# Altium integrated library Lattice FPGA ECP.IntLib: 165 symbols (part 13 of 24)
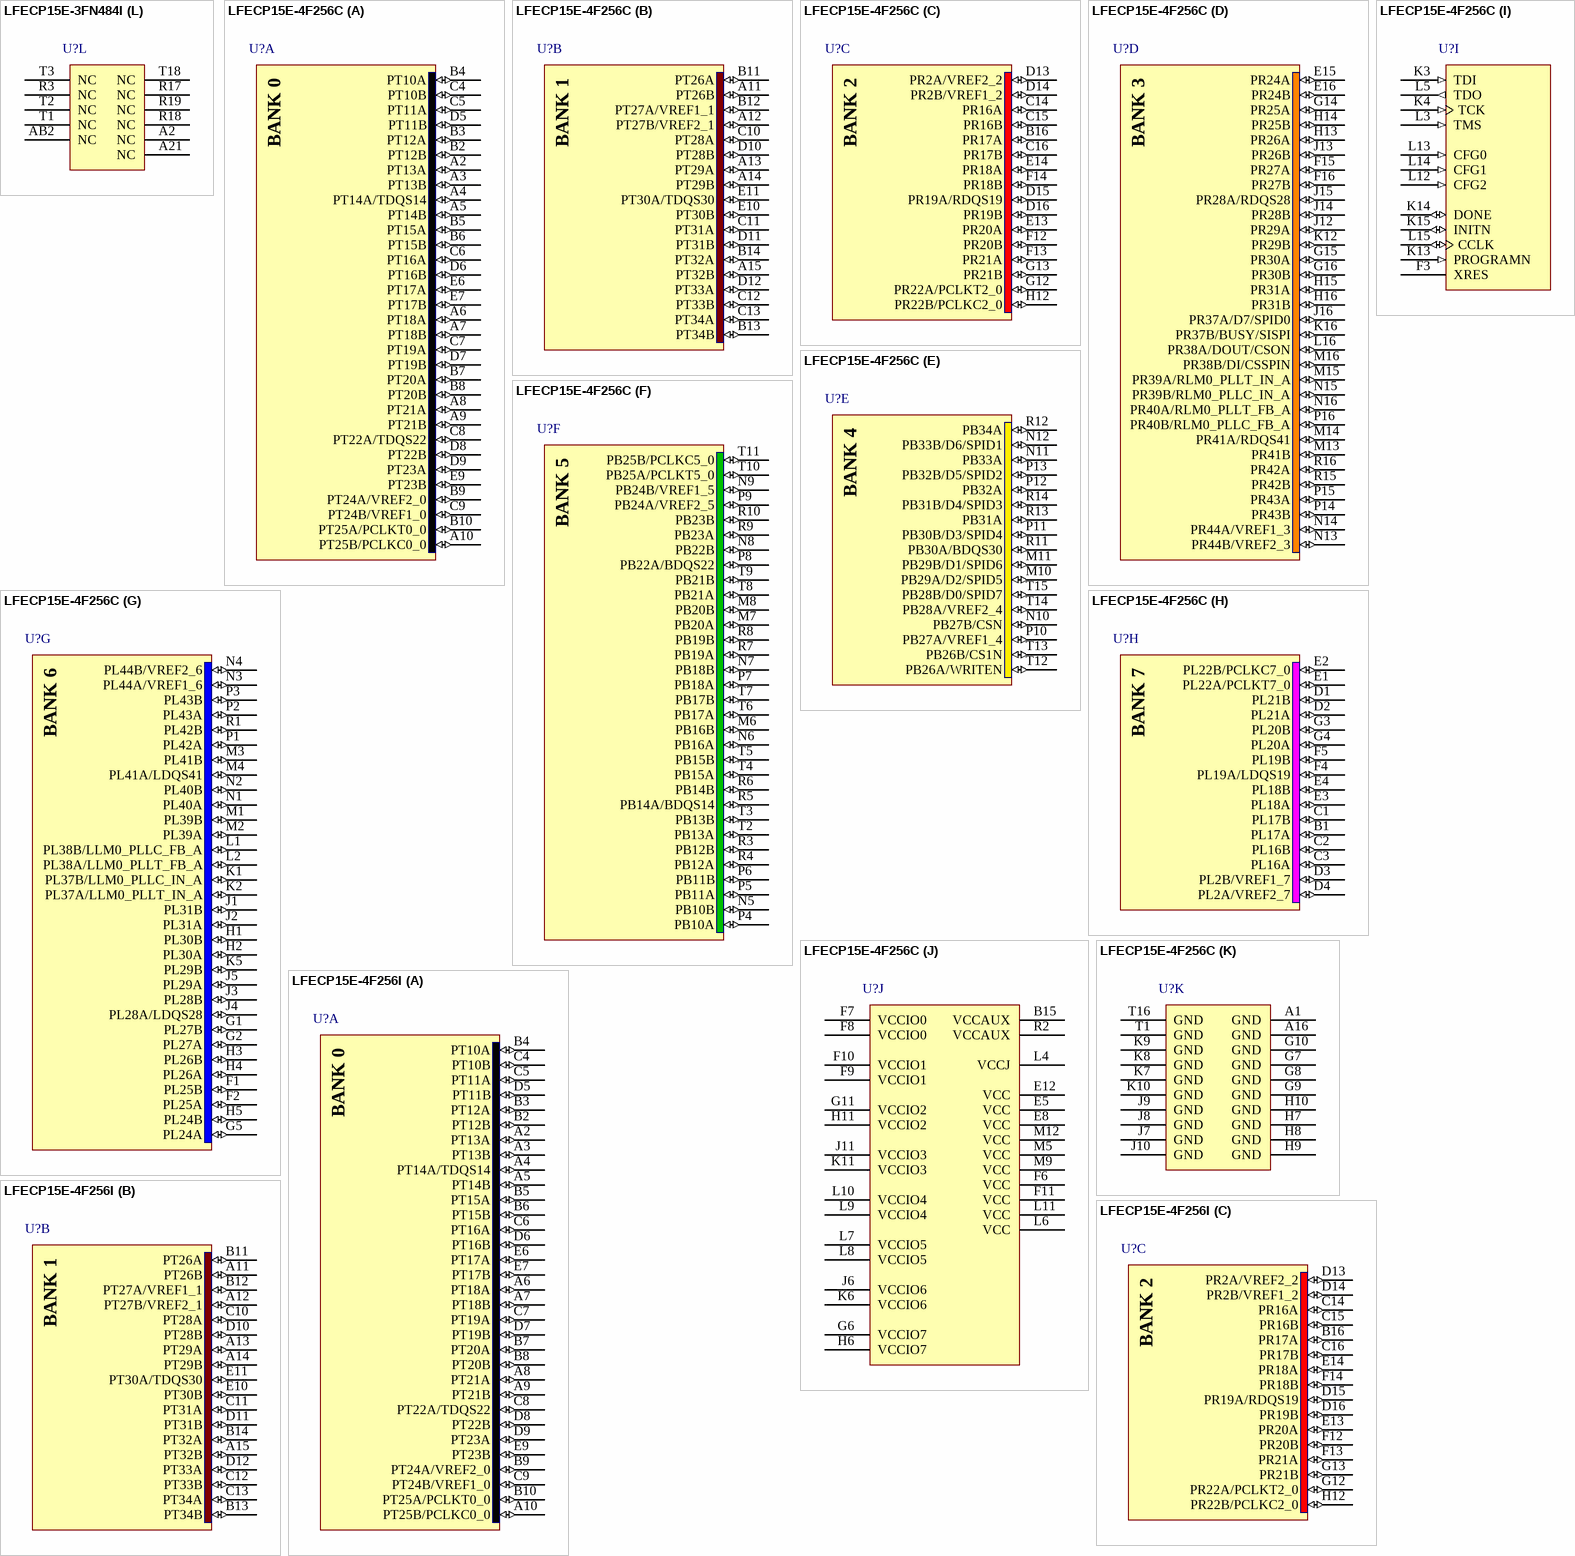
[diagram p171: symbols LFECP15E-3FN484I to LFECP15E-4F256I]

## LFECP15E-4F256C
designator U?
ECP 1.2V FPGA, 192 I/Os, 4 PLLs, 15.3K LUTs, 6 sysDSP Blocks, 24 18x18 Multipliers, 256-Pin fpBGA, Speed Grade 4, Commercial Temperature Grade
footprint fpBGA256 (BGA, 256-Leads, Body 17x17mm, Pitch 1mm)
3D model ECP15E-fpBGA256 (256-Ball Fine Pitch Ball Grid Array (fpBGA256))
part A pins: A2 PT13A (io), A3 PT13B (io), A4 PT14A/TDQS14 (io), A5 PT14B (io), A6 PT18A (io), A7 PT18B (io), A8 PT21A (io), A9 PT21B (io), A10 PT25B/PCLKC0_0 (io), B2 PT12B (io), B3 PT12A (io), B4 PT10A (io), B5 PT15A (io), B6 PT15B (io), B7 PT20A (io), B8 PT20B (io), B9 PT24A/VREF2_0 (io), B10 PT25A/PCLKT0_0 (io), C4 PT10B (io), C5 PT11A (io), C6 PT16A (io), C7 PT19A (io), C8 PT22A/TDQS22 (io), C9 PT24B/VREF1_0 (io), D5 PT11B (io), D6 PT16B (io), D7 PT19B (io), D8 PT22B (io), D9 PT23A (io), E6 PT17A (io), E7 PT17B (io), E9 PT23B (io)
part B pins: A11 PT26B (io), A12 PT27B/VREF2_1 (io), A13 PT29A (io), A14 PT29B (io), A15 PT32B (io), B11 PT26A (io), B12 PT27A/VREF1_1 (io), B13 PT34B (io), B14 PT32A (io), C10 PT28A (io), C11 PT31A (io), C12 PT33B (io), C13 PT34A (io), D10 PT28B (io), D11 PT31B (io), D12 PT33A (io), E10 PT30B (io), E11 PT30A/TDQS30 (io)
part C pins: B16 PR17A (io), C14 PR16A (io), C15 PR16B (io), C16 PR17B (io), D13 PR2A/VREF2_2 (io), D14 PR2B/VREF1_2 (io), D15 PR19A/RDQS19 (io), D16 PR19B (io), E13 PR20A (io), E14 PR18A (io), F12 PR20B (io), F13 PR21A (io), F14 PR18B (io), G12 PR22A/PCLKT2_0 (io), G13 PR21B (io), H12 PR22B/PCLKC2_0 (io)
part D pins: E15 PR24A (io), E16 PR24B (io), F15 PR27A (io), F16 PR27B (io), G14 PR25A (io), G15 PR30A (io), G16 PR30B (io), H13 PR26A (io), H14 PR25B (io), H15 PR31A (io), H16 PR31B (io), J12 PR29A (io), J13 PR26B (io), J14 PR28B (io), J15 PR28A/RDQS28 (io), J16 PR37A/D7/SPID0 (io), K12 PR29B (io), K16 PR37B/BUSY/SISPI (io), L16 PR38A/DOUT/CSON (io), M13 PR41B (io), M14 PR41A/RDQS41 (io), M15 PR39A/RLM0_PLLT_IN_A (io), M16 PR38B/DI/CSSPIN (io), N13 PR44B/VREF2_3 (io), N14 PR44A/VREF1_3 (io), N15 PR39B/RLM0_PLLC_IN_A (io), N16 PR40A/RLM0_PLLT_FB_A (io), P14 PR43B (io), P15 PR43A (io), P16 PR40B/RLM0_PLLC_FB_A (io), R15 PR42B (io), R16 PR42A (io)
part E pins: M10 PB29A/D2/SPID5 (io), M11 PB29B/D1/SPID6 (io), N10 PB27B/CSN (io), N11 PB33A (io), N12 PB33B/D6/SPID1 (io), P10 PB27A/VREF1_4 (io), P11 PB30B/D3/SPID4 (io), P12 PB32A (io), P13 PB32B/D5/SPID2 (io), R11 PB30A/BDQS30 (io), R12 PB34A (io), R13 PB31A (io), R14 PB31B/D4/SPID3 (io), T12 PB26A/WRITEN (io), T13 PB26B/CS1N (io), T14 PB28A/VREF2_4 (io), T15 PB28B/D0/SPID7 (io)
part F pins: M6 PB16B (io), M7 PB20A (io), M8 PB20B (io), N5 PB10B (io), N6 PB16A (io), N7 PB18B (io), N8 PB22B (io), N9 PB24B/VREF1_5 (io), P4 PB10A (io), P5 PB11A (io), P6 PB11B (io), P7 PB18A (io), P8 PB22A/BDQS22 (io), P9 PB24A/VREF2_5 (io), R3 PB12B (io), R4 PB12A (io), R5 PB14A/BDQS14 (io), R6 PB14B (io), R7 PB19A (io), R8 PB19B (io), R9 PB23A (io), R10 PB23B (io), T2 PB13A (io), T3 PB13B (io), T4 PB15A (io), T5 PB15B (io), T6 PB17A (io), T7 PB17B (io), T8 PB21A (io), T9 PB21B (io), T10 PB25A/PCLKT5_0 (io), T11 PB25B/PCLKC5_0 (io)
part G pins: F1 PL25B (io), F2 PL25A (io), G1 PL27B (io), G2 PL27A (io), G5 PL24A (io), H1 PL30B (io), H2 PL30A (io), H3 PL26B (io), H4 PL26A (io), H5 PL24B (io), J1 PL31B (io), J2 PL31A (io), J3 PL28B (io), J4 PL28A/LDQS28 (io), J5 PL29A (io), K1 PL37B/LLM0_PLLC_IN_A (io), K2 PL37A/LLM0_PLLT_IN_A (io), K5 PL29B (io), L1 PL38B/LLM0_PLLC_FB_A (io), L2 PL38A/LLM0_PLLT_FB_A (io), M1 PL39B (io), M2 PL39A (io), M3 PL41B (io), M4 PL41A/LDQS41 (io), N1 PL40A (io), N2 PL40B (io), N3 PL44A/VREF1_6 (io), N4 PL44B/VREF2_6 (io), P1 PL42A (io), P2 PL43A (io), P3 PL43B (io), R1 PL42B (io)
part H pins: B1 PL17A (io), C1 PL17B (io), C2 PL16B (io), C3 PL16A (io), D1 PL21B (io), D2 PL21A (io), D3 PL2B/VREF1_7 (io), D4 PL2A/VREF2_7 (io), E1 PL22A/PCLKT7_0 (io), E2 PL22B/PCLKC7_0 (io), E3 PL18A (io), E4 PL18B (io), F4 PL19A/LDQS19 (io), F5 PL19B (io), G3 PL20B (io), G4 PL20A (io)
part I pins: F3 XRES, K3 TDI (in), K4 TCK (in), K13 PROGRAMN (in), K14 DONE (io), K15 INITN (io), L3 TMS (in), L5 TDO (out), L12 CFG2 (in), L13 CFG0 (in), L14 CFG1 (in), L15 CCLK (io)
part J pins: B15 VCCAUX (power), E5 VCC (power), E8 VCC (power), E12 VCC (power), F6 VCC (power), F7 VCCIO0 (power), F8 VCCIO0 (power), F9 VCCIO1 (power), F10 VCCIO1 (power), F11 VCC (power), G6 VCCIO7 (power), G11 VCCIO2 (power), H6 VCCIO7 (power), H11 VCCIO2 (power), J6 VCCIO6 (power), J11 VCCIO3 (power), K6 VCCIO6 (power), K11 VCCIO3 (power), L4 VCCJ (power), L6 VCC (power), L7 VCCIO5 (power), L8 VCCIO5 (power), L9 VCCIO4 (power), L10 VCCIO4 (power), L11 VCC (power), M5 VCC (power), M9 VCC (power), M12 VCC (power), R2 VCCAUX (power)
part K pins: A1 GND (power), A16 GND (power), G7 GND (power), G8 GND (power), G9 GND (power), G10 GND (power), H7 GND (power), H8 GND (power), H9 GND (power), H10 GND (power), J7 GND (power), J8 GND (power), J9 GND (power), J10 GND (power), K7 GND (power), K8 GND (power), K9 GND (power), K10 GND (power), T1 GND (power), T16 GND (power)

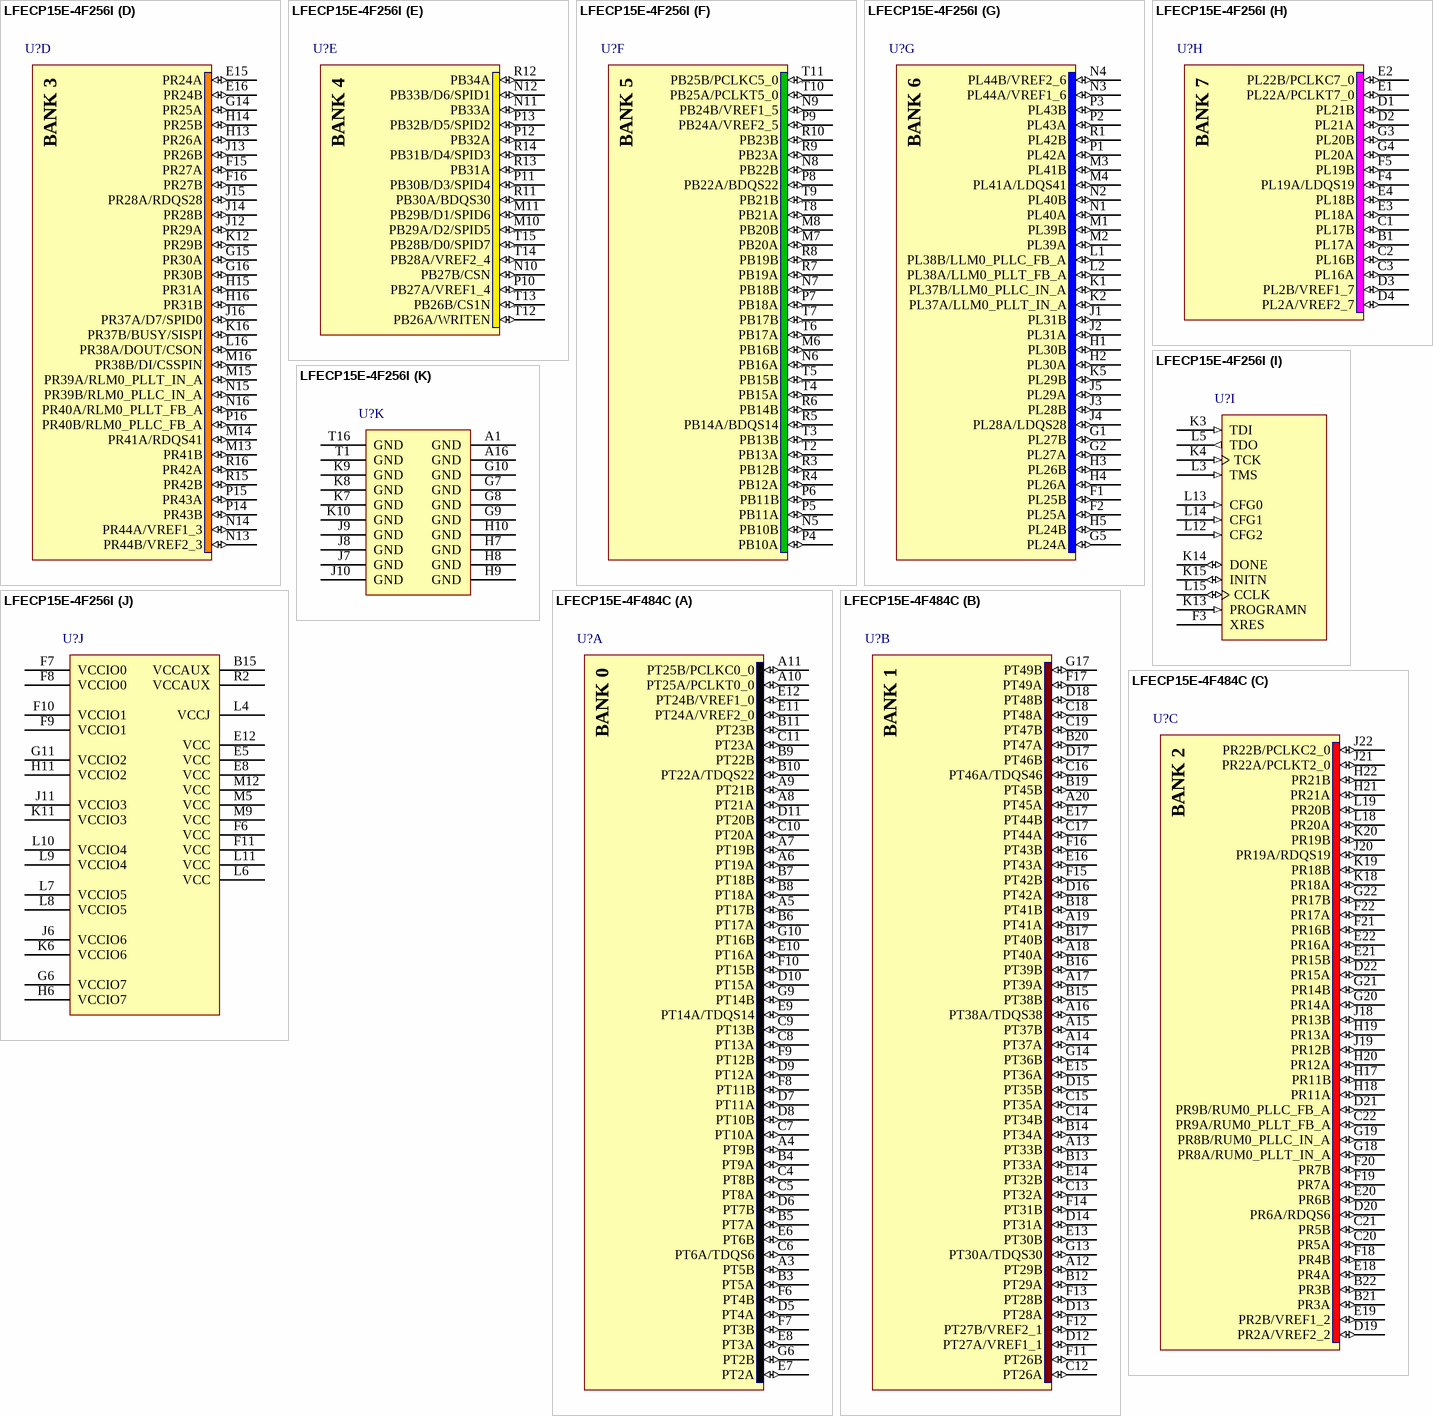
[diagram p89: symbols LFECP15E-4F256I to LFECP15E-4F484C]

## LFECP15E-4F256I
designator U?
ECP 1.2V FPGA, 192 I/Os, 4 PLLs, 15.3K LUTs, 6 sysDSP Blocks, 24 18x18 Multipliers, 256-Pin fpBGA, Speed Grade 4, Industrial Temperature Grade
footprint fpBGA256 (BGA, 256-Leads, Body 17x17mm, Pitch 1mm)
3D model ECP15E-fpBGA256 (256-Ball Fine Pitch Ball Grid Array (fpBGA256))
part A pins: A2 PT13A (io), A3 PT13B (io), A4 PT14A/TDQS14 (io), A5 PT14B (io), A6 PT18A (io), A7 PT18B (io), A8 PT21A (io), A9 PT21B (io), A10 PT25B/PCLKC0_0 (io), B2 PT12B (io), B3 PT12A (io), B4 PT10A (io), B5 PT15A (io), B6 PT15B (io), B7 PT20A (io), B8 PT20B (io), B9 PT24A/VREF2_0 (io), B10 PT25A/PCLKT0_0 (io), C4 PT10B (io), C5 PT11A (io), C6 PT16A (io), C7 PT19A (io), C8 PT22A/TDQS22 (io), C9 PT24B/VREF1_0 (io), D5 PT11B (io), D6 PT16B (io), D7 PT19B (io), D8 PT22B (io), D9 PT23A (io), E6 PT17A (io), E7 PT17B (io), E9 PT23B (io)
part B pins: A11 PT26B (io), A12 PT27B/VREF2_1 (io), A13 PT29A (io), A14 PT29B (io), A15 PT32B (io), B11 PT26A (io), B12 PT27A/VREF1_1 (io), B13 PT34B (io), B14 PT32A (io), C10 PT28A (io), C11 PT31A (io), C12 PT33B (io), C13 PT34A (io), D10 PT28B (io), D11 PT31B (io), D12 PT33A (io), E10 PT30B (io), E11 PT30A/TDQS30 (io)
part C pins: B16 PR17A (io), C14 PR16A (io), C15 PR16B (io), C16 PR17B (io), D13 PR2A/VREF2_2 (io), D14 PR2B/VREF1_2 (io), D15 PR19A/RDQS19 (io), D16 PR19B (io), E13 PR20A (io), E14 PR18A (io), F12 PR20B (io), F13 PR21A (io), F14 PR18B (io), G12 PR22A/PCLKT2_0 (io), G13 PR21B (io), H12 PR22B/PCLKC2_0 (io)
part D pins: E15 PR24A (io), E16 PR24B (io), F15 PR27A (io), F16 PR27B (io), G14 PR25A (io), G15 PR30A (io), G16 PR30B (io), H13 PR26A (io), H14 PR25B (io), H15 PR31A (io), H16 PR31B (io), J12 PR29A (io), J13 PR26B (io), J14 PR28B (io), J15 PR28A/RDQS28 (io), J16 PR37A/D7/SPID0 (io), K12 PR29B (io), K16 PR37B/BUSY/SISPI (io), L16 PR38A/DOUT/CSON (io), M13 PR41B (io), M14 PR41A/RDQS41 (io), M15 PR39A/RLM0_PLLT_IN_A (io), M16 PR38B/DI/CSSPIN (io), N13 PR44B/VREF2_3 (io), N14 PR44A/VREF1_3 (io), N15 PR39B/RLM0_PLLC_IN_A (io), N16 PR40A/RLM0_PLLT_FB_A (io), P14 PR43B (io), P15 PR43A (io), P16 PR40B/RLM0_PLLC_FB_A (io), R15 PR42B (io), R16 PR42A (io)
part E pins: M10 PB29A/D2/SPID5 (io), M11 PB29B/D1/SPID6 (io), N10 PB27B/CSN (io), N11 PB33A (io), N12 PB33B/D6/SPID1 (io), P10 PB27A/VREF1_4 (io), P11 PB30B/D3/SPID4 (io), P12 PB32A (io), P13 PB32B/D5/SPID2 (io), R11 PB30A/BDQS30 (io), R12 PB34A (io), R13 PB31A (io), R14 PB31B/D4/SPID3 (io), T12 PB26A/WRITEN (io), T13 PB26B/CS1N (io), T14 PB28A/VREF2_4 (io), T15 PB28B/D0/SPID7 (io)
part F pins: M6 PB16B (io), M7 PB20A (io), M8 PB20B (io), N5 PB10B (io), N6 PB16A (io), N7 PB18B (io), N8 PB22B (io), N9 PB24B/VREF1_5 (io), P4 PB10A (io), P5 PB11A (io), P6 PB11B (io), P7 PB18A (io), P8 PB22A/BDQS22 (io), P9 PB24A/VREF2_5 (io), R3 PB12B (io), R4 PB12A (io), R5 PB14A/BDQS14 (io), R6 PB14B (io), R7 PB19A (io), R8 PB19B (io), R9 PB23A (io), R10 PB23B (io), T2 PB13A (io), T3 PB13B (io), T4 PB15A (io), T5 PB15B (io), T6 PB17A (io), T7 PB17B (io), T8 PB21A (io), T9 PB21B (io), T10 PB25A/PCLKT5_0 (io), T11 PB25B/PCLKC5_0 (io)
part G pins: F1 PL25B (io), F2 PL25A (io), G1 PL27B (io), G2 PL27A (io), G5 PL24A (io), H1 PL30B (io), H2 PL30A (io), H3 PL26B (io), H4 PL26A (io), H5 PL24B (io), J1 PL31B (io), J2 PL31A (io), J3 PL28B (io), J4 PL28A/LDQS28 (io), J5 PL29A (io), K1 PL37B/LLM0_PLLC_IN_A (io), K2 PL37A/LLM0_PLLT_IN_A (io), K5 PL29B (io), L1 PL38B/LLM0_PLLC_FB_A (io), L2 PL38A/LLM0_PLLT_FB_A (io), M1 PL39B (io), M2 PL39A (io), M3 PL41B (io), M4 PL41A/LDQS41 (io), N1 PL40A (io), N2 PL40B (io), N3 PL44A/VREF1_6 (io), N4 PL44B/VREF2_6 (io), P1 PL42A (io), P2 PL43A (io), P3 PL43B (io), R1 PL42B (io)
part H pins: B1 PL17A (io), C1 PL17B (io), C2 PL16B (io), C3 PL16A (io), D1 PL21B (io), D2 PL21A (io), D3 PL2B/VREF1_7 (io), D4 PL2A/VREF2_7 (io), E1 PL22A/PCLKT7_0 (io), E2 PL22B/PCLKC7_0 (io), E3 PL18A (io), E4 PL18B (io), F4 PL19A/LDQS19 (io), F5 PL19B (io), G3 PL20B (io), G4 PL20A (io)
part I pins: F3 XRES, K3 TDI (in), K4 TCK (in), K13 PROGRAMN (in), K14 DONE (io), K15 INITN (io), L3 TMS (in), L5 TDO (out), L12 CFG2 (in), L13 CFG0 (in), L14 CFG1 (in), L15 CCLK (io)
part J pins: B15 VCCAUX (power), E5 VCC (power), E8 VCC (power), E12 VCC (power), F6 VCC (power), F7 VCCIO0 (power), F8 VCCIO0 (power), F9 VCCIO1 (power), F10 VCCIO1 (power), F11 VCC (power), G6 VCCIO7 (power), G11 VCCIO2 (power), H6 VCCIO7 (power), H11 VCCIO2 (power), J6 VCCIO6 (power), J11 VCCIO3 (power), K6 VCCIO6 (power), K11 VCCIO3 (power), L4 VCCJ (power), L6 VCC (power), L7 VCCIO5 (power), L8 VCCIO5 (power), L9 VCCIO4 (power), L10 VCCIO4 (power), L11 VCC (power), M5 VCC (power), M9 VCC (power), M12 VCC (power), R2 VCCAUX (power)
part K pins: A1 GND (power), A16 GND (power), G7 GND (power), G8 GND (power), G9 GND (power), G10 GND (power), H7 GND (power), H8 GND (power), H9 GND (power), H10 GND (power), J7 GND (power), J8 GND (power), J9 GND (power), J10 GND (power), K7 GND (power), K8 GND (power), K9 GND (power), K10 GND (power), T1 GND (power), T16 GND (power)

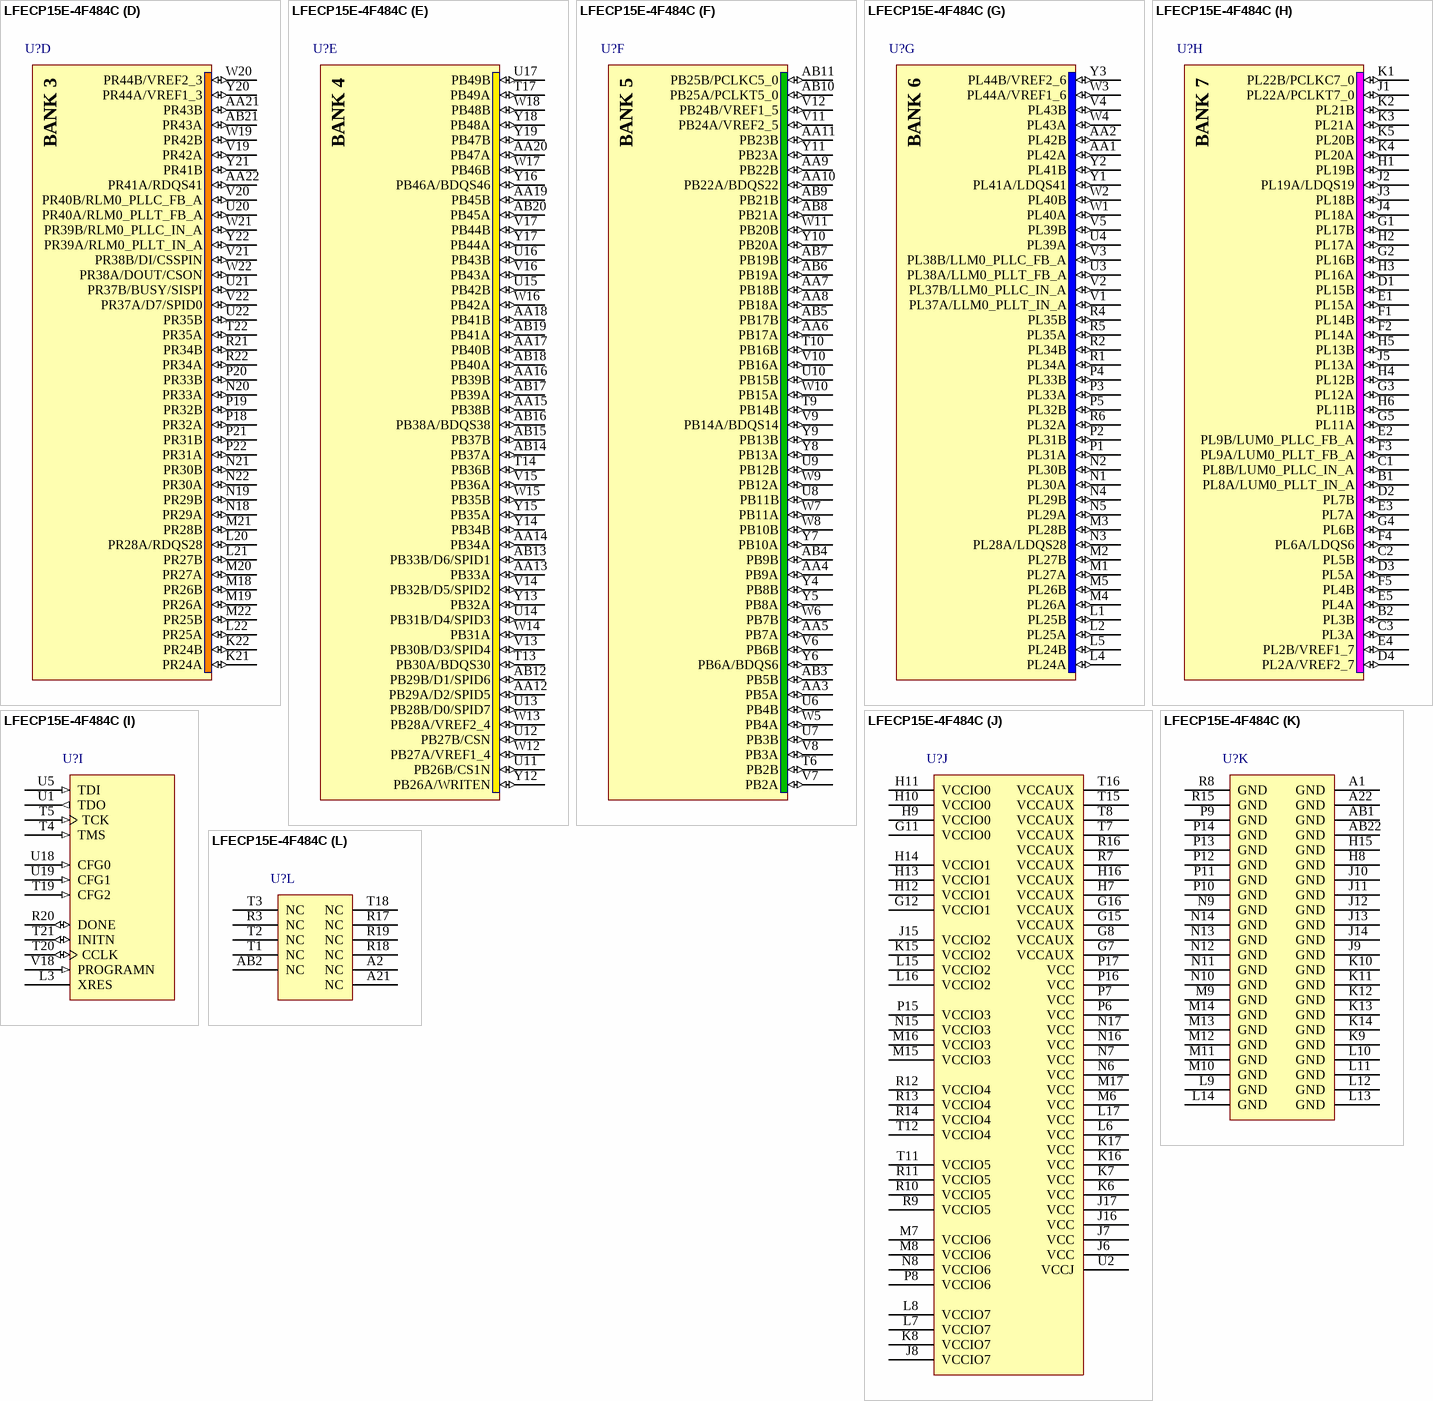
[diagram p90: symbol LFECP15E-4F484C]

## LFECP15E-4F484C
designator U?
ECP 1.2V FPGA, 352 I/Os, 4 PLLs, 15.3K LUTs, 6 sysDSP Blocks, 24 18x18 Multipliers, 484-Pin fpBGA, Speed Grade 4, Commercial Temperature Grade
footprint fpBGA484 (BGA, 484-Leads, Body 23x23mm, Pitch 1mm)
3D model ECP15E-fpBGA484 (484-Ball Fine Pitch Ball Grid Array (fpBGA484))
part A pins: A3 PT5B (io), A4 PT9B (io), A5 PT17B (io), A6 PT19A (io), A7 PT19B (io), A8 PT21A (io), A9 PT21B (io), A10 PT25A/PCLKT0_0 (io), A11 PT25B/PCLKC0_0 (io), B3 PT5A (io), B4 PT9A (io), B5 PT7A (io), B6 PT17A (io), B7 PT18B (io), B8 PT18A (io), B9 PT22B (io), B10 PT22A/TDQS22 (io), B11 PT23B (io), C4 PT8B (io), C5 PT8A (io), C6 PT6A/TDQS6 (io), C7 PT10A (io), C8 PT13A (io), C9 PT13B (io), C10 PT20A (io), C11 PT23A (io), D5 PT4A (io), D6 PT7B (io), D7 PT11A (io), D8 PT10B (io), D9 PT12A (io), D10 PT15A (io), D11 PT20B (io), E6 PT6B (io), E7 PT2A (io), E8 PT3A (io), E9 PT14A/TDQS14 (io), E10 PT16A (io), E11 PT24A/VREF2_0 (io), E12 PT24B/VREF1_0 (io), F6 PT4B (io), F7 PT3B (io), F8 PT11B (io), F9 PT12B (io), F10 PT15B (io), G6 PT2B (io), G9 PT14B (io), G10 PT16B (io)
part B pins: A12 PT29B (io), A13 PT33B (io), A14 PT37A (io), A15 PT37B (io), A16 PT38A/TDQS38 (io), A17 PT39A (io), A18 PT40A (io), A19 PT41A (io), A20 PT45A (io), B12 PT29A (io), B13 PT33A (io), B14 PT34A (io), B15 PT38B (io), B16 PT39B (io), B17 PT40B (io), B18 PT41B (io), B19 PT45B (io), B20 PT47A (io), C12 PT26A (io), C13 PT32A (io), C14 PT34B (io), C15 PT35A (io), C16 PT46A/TDQS46 (io), C17 PT44A (io), C18 PT48A (io), C19 PT47B (io), D12 PT27A/VREF1_1 (io), D13 PT28A (io), D14 PT31A (io), D15 PT35B (io), D16 PT42A (io), D17 PT46B (io), D18 PT48B (io), E13 PT30B (io), E14 PT32B (io), E15 PT36A (io), E16 PT43A (io), E17 PT44B (io), F11 PT26B (io), F12 PT27B/VREF2_1 (io), F13 PT28B (io), F14 PT31B (io), F15 PT42B (io), F16 PT43B (io), F17 PT49A (io), G13 PT30A/TDQS30 (io), G14 PT36B (io), G17 PT49B (io)
part C pins: B21 PR3A (io), B22 PR3B (io), C20 PR5A (io), C21 PR5B (io), C22 PR9A/RUM0_PLLT_FB_A (io), D19 PR2A/VREF2_2 (io), D20 PR6A/RDQS6 (io), D21 PR9B/RUM0_PLLC_FB_A (io), D22 PR15A (io), E18 PR4A (io), E19 PR2B/VREF1_2 (io), E20 PR6B (io), E21 PR15B (io), E22 PR16A (io), F18 PR4B (io), F19 PR7A (io), F20 PR7B (io), F21 PR16B (io), F22 PR17A (io), G18 PR8A/RUM0_PLLT_IN_A (io), G19 PR8B/RUM0_PLLC_IN_A (io), G20 PR14A (io), G21 PR14B (io), G22 PR17B (io), H17 PR11B (io), H18 PR11A (io), H19 PR13A (io), H20 PR12A (io), H21 PR21A (io), H22 PR21B (io), J18 PR13B (io), J19 PR12B (io), J20 PR19A/RDQS19 (io), J21 PR22A/PCLKT2_0 (io), J22 PR22B/PCLKC2_0 (io), K18 PR18A (io), K19 PR18B (io), K20 PR19B (io), L18 PR20A (io), L19 PR20B (io)
part D pins: AA21 PR43B (io), AA22 PR41A/RDQS41 (io), AB21 PR43A (io), K21 PR24A (io), K22 PR24B (io), L20 PR28A/RDQS28 (io), L21 PR27B (io), L22 PR25A (io), M18 PR26B (io), M19 PR26A (io), M20 PR27A (io), M21 PR28B (io), M22 PR25B (io), N18 PR29A (io), N19 PR29B (io), N20 PR33A (io), N21 PR30B (io), N22 PR30A (io), P18 PR32A (io), P19 PR32B (io), P20 PR33B (io), P21 PR31B (io), P22 PR31A (io), R21 PR34B (io), R22 PR34A (io), T22 PR35A (io), U20 PR40A/RLM0_PLLT_FB_A (io), U21 PR37B/BUSY/SISPI (io), U22 PR35B (io), V19 PR42A (io), V20 PR40B/RLM0_PLLC_FB_A (io), V21 PR38B/DI/CSSPIN (io), V22 PR37A/D7/SPID0 (io), W19 PR42B (io), W20 PR44B/VREF2_3 (io), W21 PR39B/RLM0_PLLC_IN_A (io), W22 PR38A/DOUT/CSON (io), Y20 PR44A/VREF1_3 (io), Y21 PR41B (io), Y22 PR39A/RLM0_PLLT_IN_A (io)
part E pins: AA12 PB29A/D2/SPID5 (io), AA13 PB33A (io), AA14 PB34A (io), AA15 PB38B (io), AA16 PB39B (io), AA17 PB40B (io), AA18 PB41B (io), AA19 PB45B (io), AA20 PB47A (io), AB12 PB29B/D1/SPID6 (io), AB13 PB33B/D6/SPID1 (io), AB14 PB37A (io), AB15 PB37B (io), AB16 PB38A/BDQS38 (io), AB17 PB39A (io), AB18 PB40A (io), AB19 PB41A (io), AB20 PB45A (io), T13 PB30A/BDQS30 (io), T14 PB36B (io), T17 PB49A (io), U11 PB26B/CS1N (io), U12 PB27B/CSN (io), U13 PB28B/D0/SPID7 (io), U14 PB31B/D4/SPID3 (io), U15 PB42B (io), U16 PB43B (io), U17 PB49B (io), V13 PB30B/D3/SPID4 (io), V14 PB32B/D5/SPID2 (io), V15 PB36A (io), V16 PB43A (io), V17 PB44B (io), W12 PB27A/VREF1_4 (io), W13 PB28A/VREF2_4 (io), W14 PB31A (io), W15 PB35B (io), W16 PB42A (io), W17 PB46B (io), W18 PB48B (io), Y12 PB26A/WRITEN (io), Y13 PB32A (io), Y14 PB34B (io), Y15 PB35A (io), Y16 PB46A/BDQS46 (io), Y17 PB44A (io), Y18 PB48A (io), Y19 PB47B (io)
part F pins: AA3 PB5A (io), AA4 PB9A (io), AA5 PB7A (io), AA6 PB17A (io), AA7 PB18B (io), AA8 PB18A (io), AA9 PB22B (io), AA10 PB22A/BDQS22 (io), AA11 PB23B (io), AB3 PB5B (io), AB4 PB9B (io), AB5 PB17B (io), AB6 PB19A (io), AB7 PB19B (io), AB8 PB21A (io), AB9 PB21B (io), AB10 PB25A/PCLKT5_0 (io), AB11 PB25B/PCLKC5_0 (io), T6 PB2B (io), T9 PB14B (io), T10 PB16B (io), U6 PB4B (io), U7 PB3B (io), U8 PB11B (io), U9 PB12B (io), U10 PB15B (io), V6 PB6B (io), V7 PB2A (io), V8 PB3A (io), V9 PB14A/BDQS14 (io), V10 PB16A (io), V11 PB24A/VREF2_5 (io), V12 PB24B/VREF1_5 (io), W5 PB4A (io), W6 PB7B (io), W7 PB11A (io), W8 PB10B (io), W9 PB12A (io), W10 PB15A (io), W11 PB20B (io), Y4 PB8B (io), Y5 PB8A (io), Y6 PB6A/BDQS6 (io), Y7 PB10A (io), Y8 PB13A (io), Y9 PB13B (io), Y10 PB20A (io), Y11 PB23A (io)
part G pins: AA1 PL42A (io), AA2 PL42B (io), L1 PL25B (io), L2 PL25A (io), L4 PL24A (io), L5 PL24B (io), M1 PL27A (io), M2 PL27B (io), M3 PL28B (io), M4 PL26A (io), M5 PL26B (io), N1 PL30A (io), N2 PL30B (io), N3 PL28A/LDQS28 (io), N4 PL29B (io), N5 PL29A (io), P1 PL31A (io), P2 PL31B (io), P3 PL33A (io), P4 PL33B (io), P5 PL32B (io), R1 PL34A (io), R2 PL34B (io), R4 PL35B (io), R5 PL35A (io), R6 PL32A (io), U3 PL38A/LLM0_PLLT_FB_A (io), U4 PL39A (io), V1 PL37A/LLM0_PLLT_IN_A (io), V2 PL37B/LLM0_PLLC_IN_A (io), V3 PL38B/LLM0_PLLC_FB_A (io), V4 PL43B (io), V5 PL39B (io), W1 PL40A (io), W2 PL40B (io), W3 PL44A/VREF1_6 (io), W4 PL43A (io), Y1 PL41A/LDQS41 (io), Y2 PL41B (io), Y3 PL44B/VREF2_6 (io)
part H pins: B1 PL8A/LUM0_PLLT_IN_A (io), B2 PL3B (io), C1 PL8B/LUM0_PLLC_IN_A (io), C2 PL5B (io), C3 PL3A (io), D1 PL15B (io), D2 PL7B (io), D3 PL5A (io), D4 PL2A/VREF2_7 (io), E1 PL15A (io), E2 PL9B/LUM0_PLLC_FB_A (io), E3 PL7A (io), E4 PL2B/VREF1_7 (io), E5 PL4A (io), F1 PL14B (io), F2 PL14A (io), F3 PL9A/LUM0_PLLT_FB_A (io), F4 PL6A/LDQS6 (io), F5 PL4B (io), G1 PL17B (io), G2 PL16B (io), G3 PL12A (io), G4 PL6B (io), G5 PL11A (io), H1 PL19B (io), H2 PL17A (io), H3 PL16A (io), H4 PL12B (io), H5 PL13B (io), H6 PL11B (io), J1 PL22A/PCLKT7_0 (io), J2 PL19A/LDQS19 (io), J3 PL18B (io), J4 PL18A (io), J5 PL13A (io), K1 PL22B/PCLKC7_0 (io), K2 PL21B (io), K3 PL21A (io), K4 PL20A (io), K5 PL20B (io)
part I pins: L3 XRES, R20 DONE (io), T4 TMS (in), T5 TCK (in), T19 CFG2 (in), T20 CCLK (io), T21 INITN (io), U1 TDO (out), U5 TDI (in), U18 CFG0 (in), U19 CFG1 (in), V18 PROGRAMN (in)
part J pins: G7 VCCAUX (power), G8 VCCAUX (power), G11 VCCIO0 (power), G12 VCCIO1 (power), G15 VCCAUX (power), G16 VCCAUX (power), H7 VCCAUX (power), H9 VCCIO0 (power), H10 VCCIO0 (power), H11 VCCIO0 (power), H12 VCCIO1 (power), H13 VCCIO1 (power), H14 VCCIO1 (power), H16 VCCAUX (power), J6 VCC (power), J7 VCC (power), J8 VCCIO7 (power), J15 VCCIO2 (power), J16 VCC (power), J17 VCC (power), K6 VCC (power), K7 VCC (power), K8 VCCIO7 (power), K15 VCCIO2 (power), K16 VCC (power), K17 VCC (power), L6 VCC (power), L7 VCCIO7 (power), L8 VCCIO7 (power), L15 VCCIO2 (power), L16 VCCIO2 (power), L17 VCC (power), M6 VCC (power), M7 VCCIO6 (power), M8 VCCIO6 (power), M15 VCCIO3 (power), M16 VCCIO3 (power), M17 VCC (power), N6 VCC (power), N7 VCC (power), N8 VCCIO6 (power), N15 VCCIO3 (power), N16 VCC (power), N17 VCC (power), P6 VCC (power), P7 VCC (power), P8 VCCIO6 (power), P15 VCCIO3 (power), P16 VCC (power), P17 VCC (power), R7 VCCAUX (power), R9 VCCIO5 (power), R10 VCCIO5 (power), R11 VCCIO5 (power), R12 VCCIO4 (power), R13 VCCIO4 (power), R14 VCCIO4 (power), R16 VCCAUX (power), T7 VCCAUX (power), T8 VCCAUX (power), T11 VCCIO5 (power), T12 VCCIO4 (power), T15 VCCAUX (power), T16 VCCAUX (power), U2 VCCJ (power)
part K pins: A1 GND (power), A22 GND (power), AB1 GND (power), AB22 GND (power), H8 GND (power), H15 GND (power), J9 GND (power), J10 GND (power), J11 GND (power), J12 GND (power), J13 GND (power), J14 GND (power), K9 GND (power), K10 GND (power), K11 GND (power), K12 GND (power), K13 GND (power), K14 GND (power), L9 GND (power), L10 GND (power), L11 GND (power), L12 GND (power), L13 GND (power), L14 GND (power), M9 GND (power), M10 GND (power), M11 GND (power), M12 GND (power), M13 GND (power), M14 GND (power), N9 GND (power), N10 GND (power), N11 GND (power), N12 GND (power), N13 GND (power), N14 GND (power), P9 GND (power), P10 GND (power), P11 GND (power), P12 GND (power), P13 GND (power), P14 GND (power), R8 GND (power), R15 GND (power)
part L pins: A2 NC, A21 NC, AB2 NC, R3 NC, R17 NC, R18 NC, R19 NC, T1 NC, T2 NC, T3 NC, T18 NC

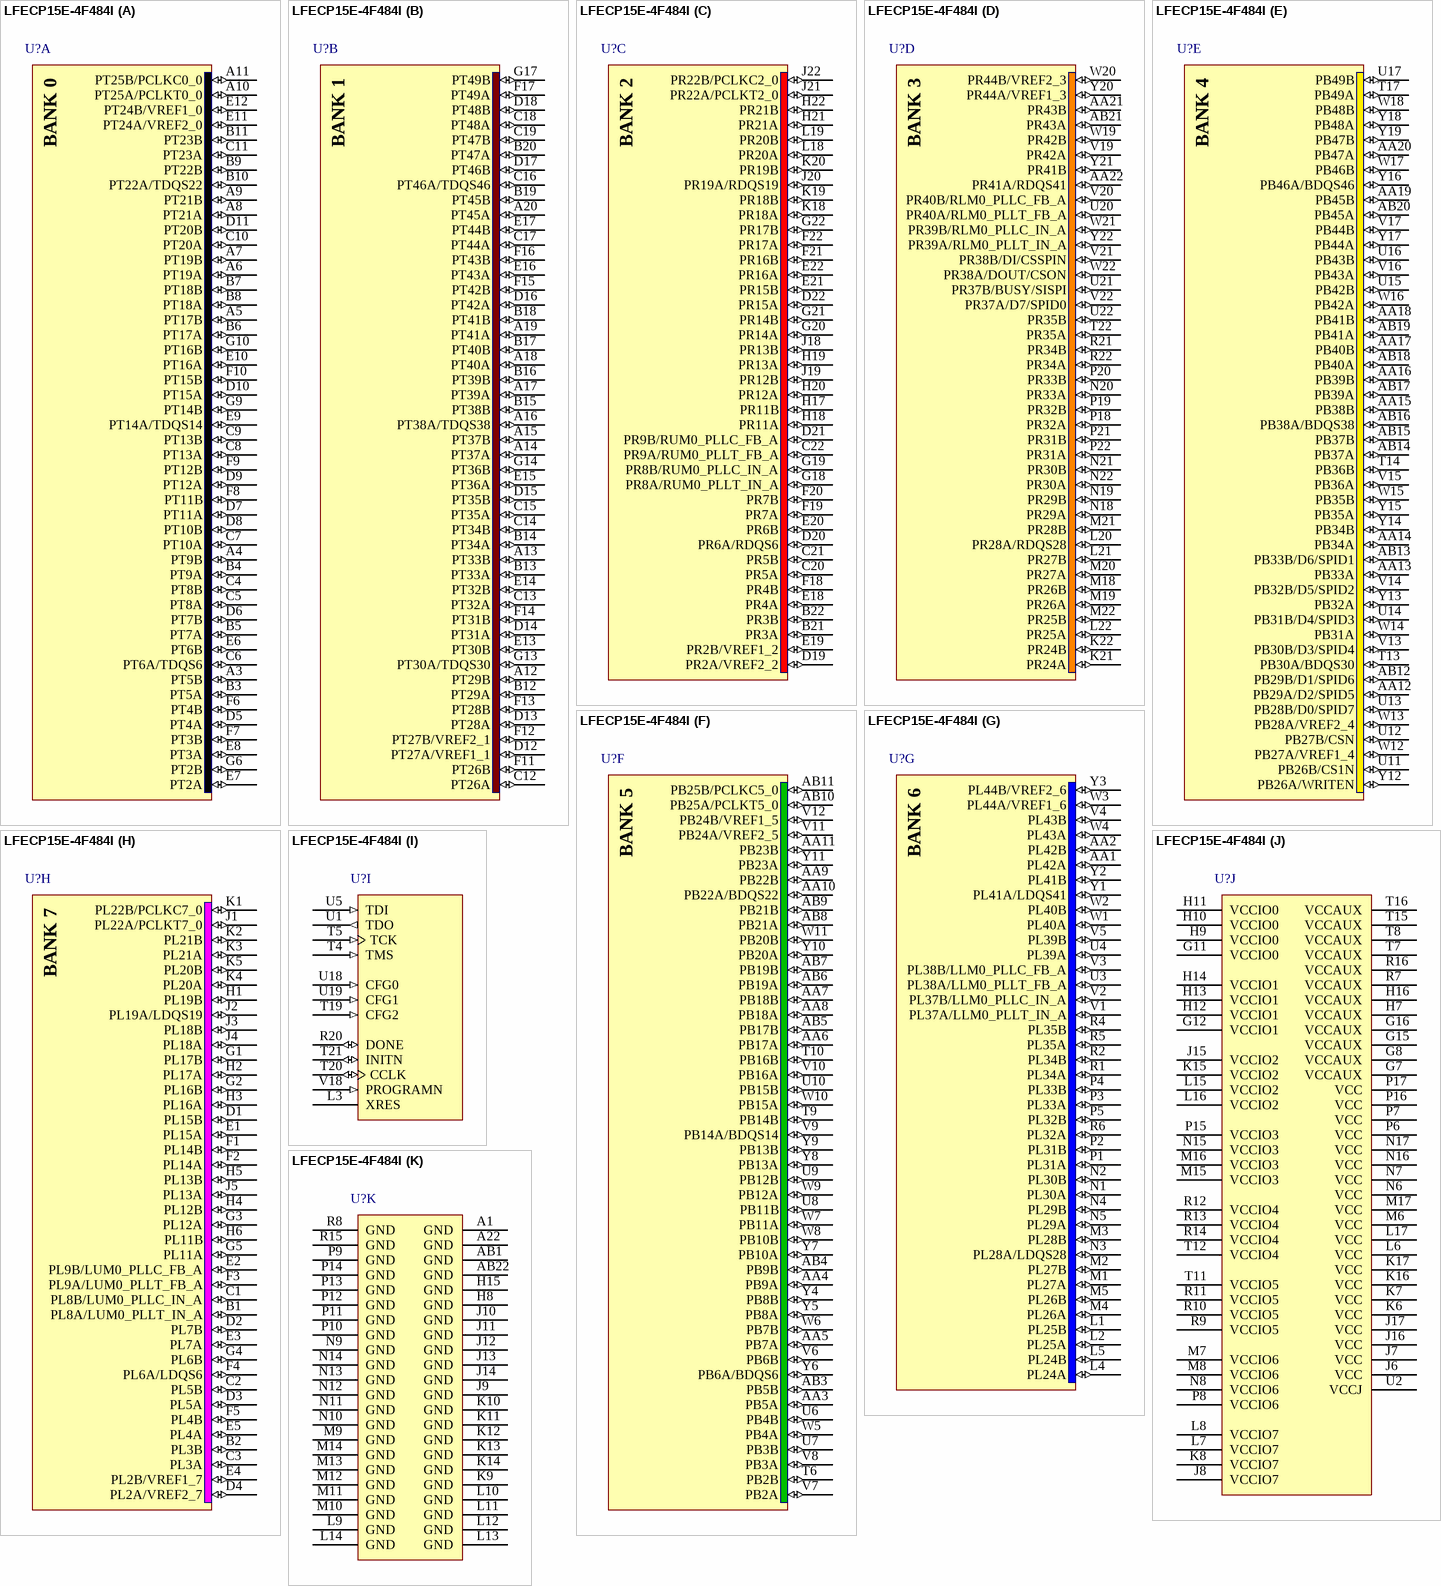
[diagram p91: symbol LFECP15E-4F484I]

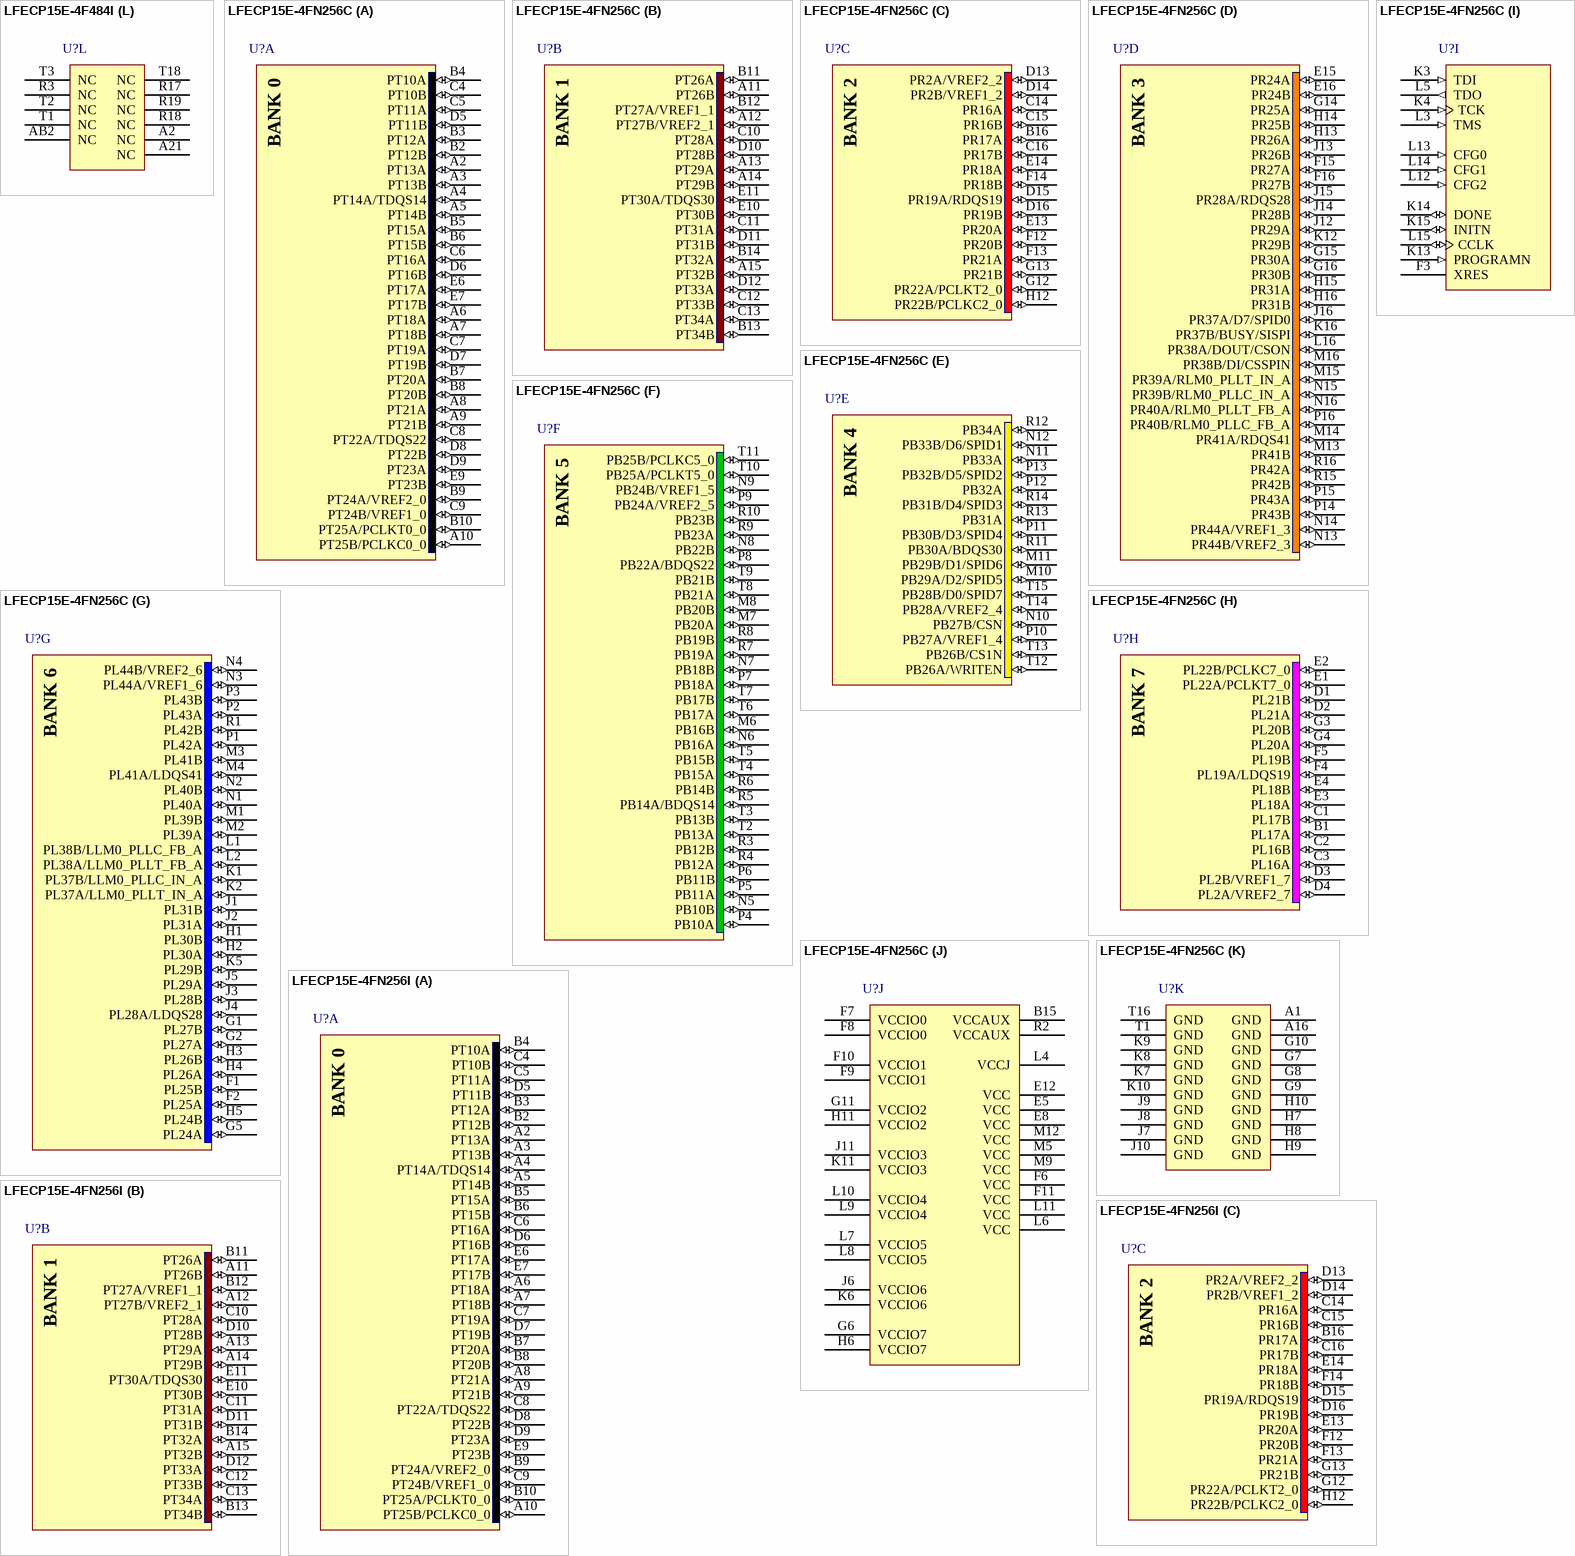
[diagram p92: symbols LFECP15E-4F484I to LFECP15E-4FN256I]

## LFECP15E-4F484I
designator U?
ECP 1.2V FPGA, 352 I/Os, 4 PLLs, 15.3K LUTs, 6 sysDSP Blocks, 24 18x18 Multipliers, 484-Pin fpBGA, Speed Grade 4, Industrial Temperature Grade
footprint fpBGA484 (BGA, 484-Leads, Body 23x23mm, Pitch 1mm)
3D model ECP15E-fpBGA484 (484-Ball Fine Pitch Ball Grid Array (fpBGA484))
part A pins: A3 PT5B (io), A4 PT9B (io), A5 PT17B (io), A6 PT19A (io), A7 PT19B (io), A8 PT21A (io), A9 PT21B (io), A10 PT25A/PCLKT0_0 (io), A11 PT25B/PCLKC0_0 (io), B3 PT5A (io), B4 PT9A (io), B5 PT7A (io), B6 PT17A (io), B7 PT18B (io), B8 PT18A (io), B9 PT22B (io), B10 PT22A/TDQS22 (io), B11 PT23B (io), C4 PT8B (io), C5 PT8A (io), C6 PT6A/TDQS6 (io), C7 PT10A (io), C8 PT13A (io), C9 PT13B (io), C10 PT20A (io), C11 PT23A (io), D5 PT4A (io), D6 PT7B (io), D7 PT11A (io), D8 PT10B (io), D9 PT12A (io), D10 PT15A (io), D11 PT20B (io), E6 PT6B (io), E7 PT2A (io), E8 PT3A (io), E9 PT14A/TDQS14 (io), E10 PT16A (io), E11 PT24A/VREF2_0 (io), E12 PT24B/VREF1_0 (io), F6 PT4B (io), F7 PT3B (io), F8 PT11B (io), F9 PT12B (io), F10 PT15B (io), G6 PT2B (io), G9 PT14B (io), G10 PT16B (io)
part B pins: A12 PT29B (io), A13 PT33B (io), A14 PT37A (io), A15 PT37B (io), A16 PT38A/TDQS38 (io), A17 PT39A (io), A18 PT40A (io), A19 PT41A (io), A20 PT45A (io), B12 PT29A (io), B13 PT33A (io), B14 PT34A (io), B15 PT38B (io), B16 PT39B (io), B17 PT40B (io), B18 PT41B (io), B19 PT45B (io), B20 PT47A (io), C12 PT26A (io), C13 PT32A (io), C14 PT34B (io), C15 PT35A (io), C16 PT46A/TDQS46 (io), C17 PT44A (io), C18 PT48A (io), C19 PT47B (io), D12 PT27A/VREF1_1 (io), D13 PT28A (io), D14 PT31A (io), D15 PT35B (io), D16 PT42A (io), D17 PT46B (io), D18 PT48B (io), E13 PT30B (io), E14 PT32B (io), E15 PT36A (io), E16 PT43A (io), E17 PT44B (io), F11 PT26B (io), F12 PT27B/VREF2_1 (io), F13 PT28B (io), F14 PT31B (io), F15 PT42B (io), F16 PT43B (io), F17 PT49A (io), G13 PT30A/TDQS30 (io), G14 PT36B (io), G17 PT49B (io)
part C pins: B21 PR3A (io), B22 PR3B (io), C20 PR5A (io), C21 PR5B (io), C22 PR9A/RUM0_PLLT_FB_A (io), D19 PR2A/VREF2_2 (io), D20 PR6A/RDQS6 (io), D21 PR9B/RUM0_PLLC_FB_A (io), D22 PR15A (io), E18 PR4A (io), E19 PR2B/VREF1_2 (io), E20 PR6B (io), E21 PR15B (io), E22 PR16A (io), F18 PR4B (io), F19 PR7A (io), F20 PR7B (io), F21 PR16B (io), F22 PR17A (io), G18 PR8A/RUM0_PLLT_IN_A (io), G19 PR8B/RUM0_PLLC_IN_A (io), G20 PR14A (io), G21 PR14B (io), G22 PR17B (io), H17 PR11B (io), H18 PR11A (io), H19 PR13A (io), H20 PR12A (io), H21 PR21A (io), H22 PR21B (io), J18 PR13B (io), J19 PR12B (io), J20 PR19A/RDQS19 (io), J21 PR22A/PCLKT2_0 (io), J22 PR22B/PCLKC2_0 (io), K18 PR18A (io), K19 PR18B (io), K20 PR19B (io), L18 PR20A (io), L19 PR20B (io)
part D pins: AA21 PR43B (io), AA22 PR41A/RDQS41 (io), AB21 PR43A (io), K21 PR24A (io), K22 PR24B (io), L20 PR28A/RDQS28 (io), L21 PR27B (io), L22 PR25A (io), M18 PR26B (io), M19 PR26A (io), M20 PR27A (io), M21 PR28B (io), M22 PR25B (io), N18 PR29A (io), N19 PR29B (io), N20 PR33A (io), N21 PR30B (io), N22 PR30A (io), P18 PR32A (io), P19 PR32B (io), P20 PR33B (io), P21 PR31B (io), P22 PR31A (io), R21 PR34B (io), R22 PR34A (io), T22 PR35A (io), U20 PR40A/RLM0_PLLT_FB_A (io), U21 PR37B/BUSY/SISPI (io), U22 PR35B (io), V19 PR42A (io), V20 PR40B/RLM0_PLLC_FB_A (io), V21 PR38B/DI/CSSPIN (io), V22 PR37A/D7/SPID0 (io), W19 PR42B (io), W20 PR44B/VREF2_3 (io), W21 PR39B/RLM0_PLLC_IN_A (io), W22 PR38A/DOUT/CSON (io), Y20 PR44A/VREF1_3 (io), Y21 PR41B (io), Y22 PR39A/RLM0_PLLT_IN_A (io)
part E pins: AA12 PB29A/D2/SPID5 (io), AA13 PB33A (io), AA14 PB34A (io), AA15 PB38B (io), AA16 PB39B (io), AA17 PB40B (io), AA18 PB41B (io), AA19 PB45B (io), AA20 PB47A (io), AB12 PB29B/D1/SPID6 (io), AB13 PB33B/D6/SPID1 (io), AB14 PB37A (io), AB15 PB37B (io), AB16 PB38A/BDQS38 (io), AB17 PB39A (io), AB18 PB40A (io), AB19 PB41A (io), AB20 PB45A (io), T13 PB30A/BDQS30 (io), T14 PB36B (io), T17 PB49A (io), U11 PB26B/CS1N (io), U12 PB27B/CSN (io), U13 PB28B/D0/SPID7 (io), U14 PB31B/D4/SPID3 (io), U15 PB42B (io), U16 PB43B (io), U17 PB49B (io), V13 PB30B/D3/SPID4 (io), V14 PB32B/D5/SPID2 (io), V15 PB36A (io), V16 PB43A (io), V17 PB44B (io), W12 PB27A/VREF1_4 (io), W13 PB28A/VREF2_4 (io), W14 PB31A (io), W15 PB35B (io), W16 PB42A (io), W17 PB46B (io), W18 PB48B (io), Y12 PB26A/WRITEN (io), Y13 PB32A (io), Y14 PB34B (io), Y15 PB35A (io), Y16 PB46A/BDQS46 (io), Y17 PB44A (io), Y18 PB48A (io), Y19 PB47B (io)
part F pins: AA3 PB5A (io), AA4 PB9A (io), AA5 PB7A (io), AA6 PB17A (io), AA7 PB18B (io), AA8 PB18A (io), AA9 PB22B (io), AA10 PB22A/BDQS22 (io), AA11 PB23B (io), AB3 PB5B (io), AB4 PB9B (io), AB5 PB17B (io), AB6 PB19A (io), AB7 PB19B (io), AB8 PB21A (io), AB9 PB21B (io), AB10 PB25A/PCLKT5_0 (io), AB11 PB25B/PCLKC5_0 (io), T6 PB2B (io), T9 PB14B (io), T10 PB16B (io), U6 PB4B (io), U7 PB3B (io), U8 PB11B (io), U9 PB12B (io), U10 PB15B (io), V6 PB6B (io), V7 PB2A (io), V8 PB3A (io), V9 PB14A/BDQS14 (io), V10 PB16A (io), V11 PB24A/VREF2_5 (io), V12 PB24B/VREF1_5 (io), W5 PB4A (io), W6 PB7B (io), W7 PB11A (io), W8 PB10B (io), W9 PB12A (io), W10 PB15A (io), W11 PB20B (io), Y4 PB8B (io), Y5 PB8A (io), Y6 PB6A/BDQS6 (io), Y7 PB10A (io), Y8 PB13A (io), Y9 PB13B (io), Y10 PB20A (io), Y11 PB23A (io)
part G pins: AA1 PL42A (io), AA2 PL42B (io), L1 PL25B (io), L2 PL25A (io), L4 PL24A (io), L5 PL24B (io), M1 PL27A (io), M2 PL27B (io), M3 PL28B (io), M4 PL26A (io), M5 PL26B (io), N1 PL30A (io), N2 PL30B (io), N3 PL28A/LDQS28 (io), N4 PL29B (io), N5 PL29A (io), P1 PL31A (io), P2 PL31B (io), P3 PL33A (io), P4 PL33B (io), P5 PL32B (io), R1 PL34A (io), R2 PL34B (io), R4 PL35B (io), R5 PL35A (io), R6 PL32A (io), U3 PL38A/LLM0_PLLT_FB_A (io), U4 PL39A (io), V1 PL37A/LLM0_PLLT_IN_A (io), V2 PL37B/LLM0_PLLC_IN_A (io), V3 PL38B/LLM0_PLLC_FB_A (io), V4 PL43B (io), V5 PL39B (io), W1 PL40A (io), W2 PL40B (io), W3 PL44A/VREF1_6 (io), W4 PL43A (io), Y1 PL41A/LDQS41 (io), Y2 PL41B (io), Y3 PL44B/VREF2_6 (io)
part H pins: B1 PL8A/LUM0_PLLT_IN_A (io), B2 PL3B (io), C1 PL8B/LUM0_PLLC_IN_A (io), C2 PL5B (io), C3 PL3A (io), D1 PL15B (io), D2 PL7B (io), D3 PL5A (io), D4 PL2A/VREF2_7 (io), E1 PL15A (io), E2 PL9B/LUM0_PLLC_FB_A (io), E3 PL7A (io), E4 PL2B/VREF1_7 (io), E5 PL4A (io), F1 PL14B (io), F2 PL14A (io), F3 PL9A/LUM0_PLLT_FB_A (io), F4 PL6A/LDQS6 (io), F5 PL4B (io), G1 PL17B (io), G2 PL16B (io), G3 PL12A (io), G4 PL6B (io), G5 PL11A (io), H1 PL19B (io), H2 PL17A (io), H3 PL16A (io), H4 PL12B (io), H5 PL13B (io), H6 PL11B (io), J1 PL22A/PCLKT7_0 (io), J2 PL19A/LDQS19 (io), J3 PL18B (io), J4 PL18A (io), J5 PL13A (io), K1 PL22B/PCLKC7_0 (io), K2 PL21B (io), K3 PL21A (io), K4 PL20A (io), K5 PL20B (io)
part I pins: L3 XRES, R20 DONE (io), T4 TMS (in), T5 TCK (in), T19 CFG2 (in), T20 CCLK (io), T21 INITN (io), U1 TDO (out), U5 TDI (in), U18 CFG0 (in), U19 CFG1 (in), V18 PROGRAMN (in)
part J pins: G7 VCCAUX (power), G8 VCCAUX (power), G11 VCCIO0 (power), G12 VCCIO1 (power), G15 VCCAUX (power), G16 VCCAUX (power), H7 VCCAUX (power), H9 VCCIO0 (power), H10 VCCIO0 (power), H11 VCCIO0 (power), H12 VCCIO1 (power), H13 VCCIO1 (power), H14 VCCIO1 (power), H16 VCCAUX (power), J6 VCC (power), J7 VCC (power), J8 VCCIO7 (power), J15 VCCIO2 (power), J16 VCC (power), J17 VCC (power), K6 VCC (power), K7 VCC (power), K8 VCCIO7 (power), K15 VCCIO2 (power), K16 VCC (power), K17 VCC (power), L6 VCC (power), L7 VCCIO7 (power), L8 VCCIO7 (power), L15 VCCIO2 (power), L16 VCCIO2 (power), L17 VCC (power), M6 VCC (power), M7 VCCIO6 (power), M8 VCCIO6 (power), M15 VCCIO3 (power), M16 VCCIO3 (power), M17 VCC (power), N6 VCC (power), N7 VCC (power), N8 VCCIO6 (power), N15 VCCIO3 (power), N16 VCC (power), N17 VCC (power), P6 VCC (power), P7 VCC (power), P8 VCCIO6 (power), P15 VCCIO3 (power), P16 VCC (power), P17 VCC (power), R7 VCCAUX (power), R9 VCCIO5 (power), R10 VCCIO5 (power), R11 VCCIO5 (power), R12 VCCIO4 (power), R13 VCCIO4 (power), R14 VCCIO4 (power), R16 VCCAUX (power), T7 VCCAUX (power), T8 VCCAUX (power), T11 VCCIO5 (power), T12 VCCIO4 (power), T15 VCCAUX (power), T16 VCCAUX (power), U2 VCCJ (power)
part K pins: A1 GND (power), A22 GND (power), AB1 GND (power), AB22 GND (power), H8 GND (power), H15 GND (power), J9 GND (power), J10 GND (power), J11 GND (power), J12 GND (power), J13 GND (power), J14 GND (power), K9 GND (power), K10 GND (power), K11 GND (power), K12 GND (power), K13 GND (power), K14 GND (power), L9 GND (power), L10 GND (power), L11 GND (power), L12 GND (power), L13 GND (power), L14 GND (power), M9 GND (power), M10 GND (power), M11 GND (power), M12 GND (power), M13 GND (power), M14 GND (power), N9 GND (power), N10 GND (power), N11 GND (power), N12 GND (power), N13 GND (power), N14 GND (power), P9 GND (power), P10 GND (power), P11 GND (power), P12 GND (power), P13 GND (power), P14 GND (power), R8 GND (power), R15 GND (power)
part L pins: A2 NC, A21 NC, AB2 NC, R3 NC, R17 NC, R18 NC, R19 NC, T1 NC, T2 NC, T3 NC, T18 NC

## LFECP15E-4FN256C
designator U?
ECP 1.2V FPGA, 195 I/Os, 4 PLLs, 15.3K LUTs, 6 sysDSP Blocks, 24 18x18 Multipliers, 256-Pin fpBGA, Pb-Free, Speed Grade 4, Commercial Temperature Grade
footprint fpBGA256 (BGA, 256-Leads, Body 17x17mm, Pitch 1mm)
3D model ECP15E-fpBGA256 (256-Ball Fine Pitch Ball Grid Array (fpBGA256))
part A pins: A2 PT13A (io), A3 PT13B (io), A4 PT14A/TDQS14 (io), A5 PT14B (io), A6 PT18A (io), A7 PT18B (io), A8 PT21A (io), A9 PT21B (io), A10 PT25B/PCLKC0_0 (io), B2 PT12B (io), B3 PT12A (io), B4 PT10A (io), B5 PT15A (io), B6 PT15B (io), B7 PT20A (io), B8 PT20B (io), B9 PT24A/VREF2_0 (io), B10 PT25A/PCLKT0_0 (io), C4 PT10B (io), C5 PT11A (io), C6 PT16A (io), C7 PT19A (io), C8 PT22A/TDQS22 (io), C9 PT24B/VREF1_0 (io), D5 PT11B (io), D6 PT16B (io), D7 PT19B (io), D8 PT22B (io), D9 PT23A (io), E6 PT17A (io), E7 PT17B (io), E9 PT23B (io)
part B pins: A11 PT26B (io), A12 PT27B/VREF2_1 (io), A13 PT29A (io), A14 PT29B (io), A15 PT32B (io), B11 PT26A (io), B12 PT27A/VREF1_1 (io), B13 PT34B (io), B14 PT32A (io), C10 PT28A (io), C11 PT31A (io), C12 PT33B (io), C13 PT34A (io), D10 PT28B (io), D11 PT31B (io), D12 PT33A (io), E10 PT30B (io), E11 PT30A/TDQS30 (io)
part C pins: B16 PR17A (io), C14 PR16A (io), C15 PR16B (io), C16 PR17B (io), D13 PR2A/VREF2_2 (io), D14 PR2B/VREF1_2 (io), D15 PR19A/RDQS19 (io), D16 PR19B (io), E13 PR20A (io), E14 PR18A (io), F12 PR20B (io), F13 PR21A (io), F14 PR18B (io), G12 PR22A/PCLKT2_0 (io), G13 PR21B (io), H12 PR22B/PCLKC2_0 (io)
part D pins: E15 PR24A (io), E16 PR24B (io), F15 PR27A (io), F16 PR27B (io), G14 PR25A (io), G15 PR30A (io), G16 PR30B (io), H13 PR26A (io), H14 PR25B (io), H15 PR31A (io), H16 PR31B (io), J12 PR29A (io), J13 PR26B (io), J14 PR28B (io), J15 PR28A/RDQS28 (io), J16 PR37A/D7/SPID0 (io), K12 PR29B (io), K16 PR37B/BUSY/SISPI (io), L16 PR38A/DOUT/CSON (io), M13 PR41B (io), M14 PR41A/RDQS41 (io), M15 PR39A/RLM0_PLLT_IN_A (io), M16 PR38B/DI/CSSPIN (io), N13 PR44B/VREF2_3 (io), N14 PR44A/VREF1_3 (io), N15 PR39B/RLM0_PLLC_IN_A (io), N16 PR40A/RLM0_PLLT_FB_A (io), P14 PR43B (io), P15 PR43A (io), P16 PR40B/RLM0_PLLC_FB_A (io), R15 PR42B (io), R16 PR42A (io)
part E pins: M10 PB29A/D2/SPID5 (io), M11 PB29B/D1/SPID6 (io), N10 PB27B/CSN (io), N11 PB33A (io), N12 PB33B/D6/SPID1 (io), P10 PB27A/VREF1_4 (io), P11 PB30B/D3/SPID4 (io), P12 PB32A (io), P13 PB32B/D5/SPID2 (io), R11 PB30A/BDQS30 (io), R12 PB34A (io), R13 PB31A (io), R14 PB31B/D4/SPID3 (io), T12 PB26A/WRITEN (io), T13 PB26B/CS1N (io), T14 PB28A/VREF2_4 (io), T15 PB28B/D0/SPID7 (io)
part F pins: M6 PB16B (io), M7 PB20A (io), M8 PB20B (io), N5 PB10B (io), N6 PB16A (io), N7 PB18B (io), N8 PB22B (io), N9 PB24B/VREF1_5 (io), P4 PB10A (io), P5 PB11A (io), P6 PB11B (io), P7 PB18A (io), P8 PB22A/BDQS22 (io), P9 PB24A/VREF2_5 (io), R3 PB12B (io), R4 PB12A (io), R5 PB14A/BDQS14 (io), R6 PB14B (io), R7 PB19A (io), R8 PB19B (io), R9 PB23A (io), R10 PB23B (io), T2 PB13A (io), T3 PB13B (io), T4 PB15A (io), T5 PB15B (io), T6 PB17A (io), T7 PB17B (io), T8 PB21A (io), T9 PB21B (io), T10 PB25A/PCLKT5_0 (io), T11 PB25B/PCLKC5_0 (io)
part G pins: F1 PL25B (io), F2 PL25A (io), G1 PL27B (io), G2 PL27A (io), G5 PL24A (io), H1 PL30B (io), H2 PL30A (io), H3 PL26B (io), H4 PL26A (io), H5 PL24B (io), J1 PL31B (io), J2 PL31A (io), J3 PL28B (io), J4 PL28A/LDQS28 (io), J5 PL29A (io), K1 PL37B/LLM0_PLLC_IN_A (io), K2 PL37A/LLM0_PLLT_IN_A (io), K5 PL29B (io), L1 PL38B/LLM0_PLLC_FB_A (io), L2 PL38A/LLM0_PLLT_FB_A (io), M1 PL39B (io), M2 PL39A (io), M3 PL41B (io), M4 PL41A/LDQS41 (io), N1 PL40A (io), N2 PL40B (io), N3 PL44A/VREF1_6 (io), N4 PL44B/VREF2_6 (io), P1 PL42A (io), P2 PL43A (io), P3 PL43B (io), R1 PL42B (io)
part H pins: B1 PL17A (io), C1 PL17B (io), C2 PL16B (io), C3 PL16A (io), D1 PL21B (io), D2 PL21A (io), D3 PL2B/VREF1_7 (io), D4 PL2A/VREF2_7 (io), E1 PL22A/PCLKT7_0 (io), E2 PL22B/PCLKC7_0 (io), E3 PL18A (io), E4 PL18B (io), F4 PL19A/LDQS19 (io), F5 PL19B (io), G3 PL20B (io), G4 PL20A (io)
part I pins: F3 XRES, K3 TDI (in), K4 TCK (in), K13 PROGRAMN (in), K14 DONE (io), K15 INITN (io), L3 TMS (in), L5 TDO (out), L12 CFG2 (in), L13 CFG0 (in), L14 CFG1 (in), L15 CCLK (io)
part J pins: B15 VCCAUX (power), E5 VCC (power), E8 VCC (power), E12 VCC (power), F6 VCC (power), F7 VCCIO0 (power), F8 VCCIO0 (power), F9 VCCIO1 (power), F10 VCCIO1 (power), F11 VCC (power), G6 VCCIO7 (power), G11 VCCIO2 (power), H6 VCCIO7 (power), H11 VCCIO2 (power), J6 VCCIO6 (power), J11 VCCIO3 (power), K6 VCCIO6 (power), K11 VCCIO3 (power), L4 VCCJ (power), L6 VCC (power), L7 VCCIO5 (power), L8 VCCIO5 (power), L9 VCCIO4 (power), L10 VCCIO4 (power), L11 VCC (power), M5 VCC (power), M9 VCC (power), M12 VCC (power), R2 VCCAUX (power)
part K pins: A1 GND (power), A16 GND (power), G7 GND (power), G8 GND (power), G9 GND (power), G10 GND (power), H7 GND (power), H8 GND (power), H9 GND (power), H10 GND (power), J7 GND (power), J8 GND (power), J9 GND (power), J10 GND (power), K7 GND (power), K8 GND (power), K9 GND (power), K10 GND (power), T1 GND (power), T16 GND (power)

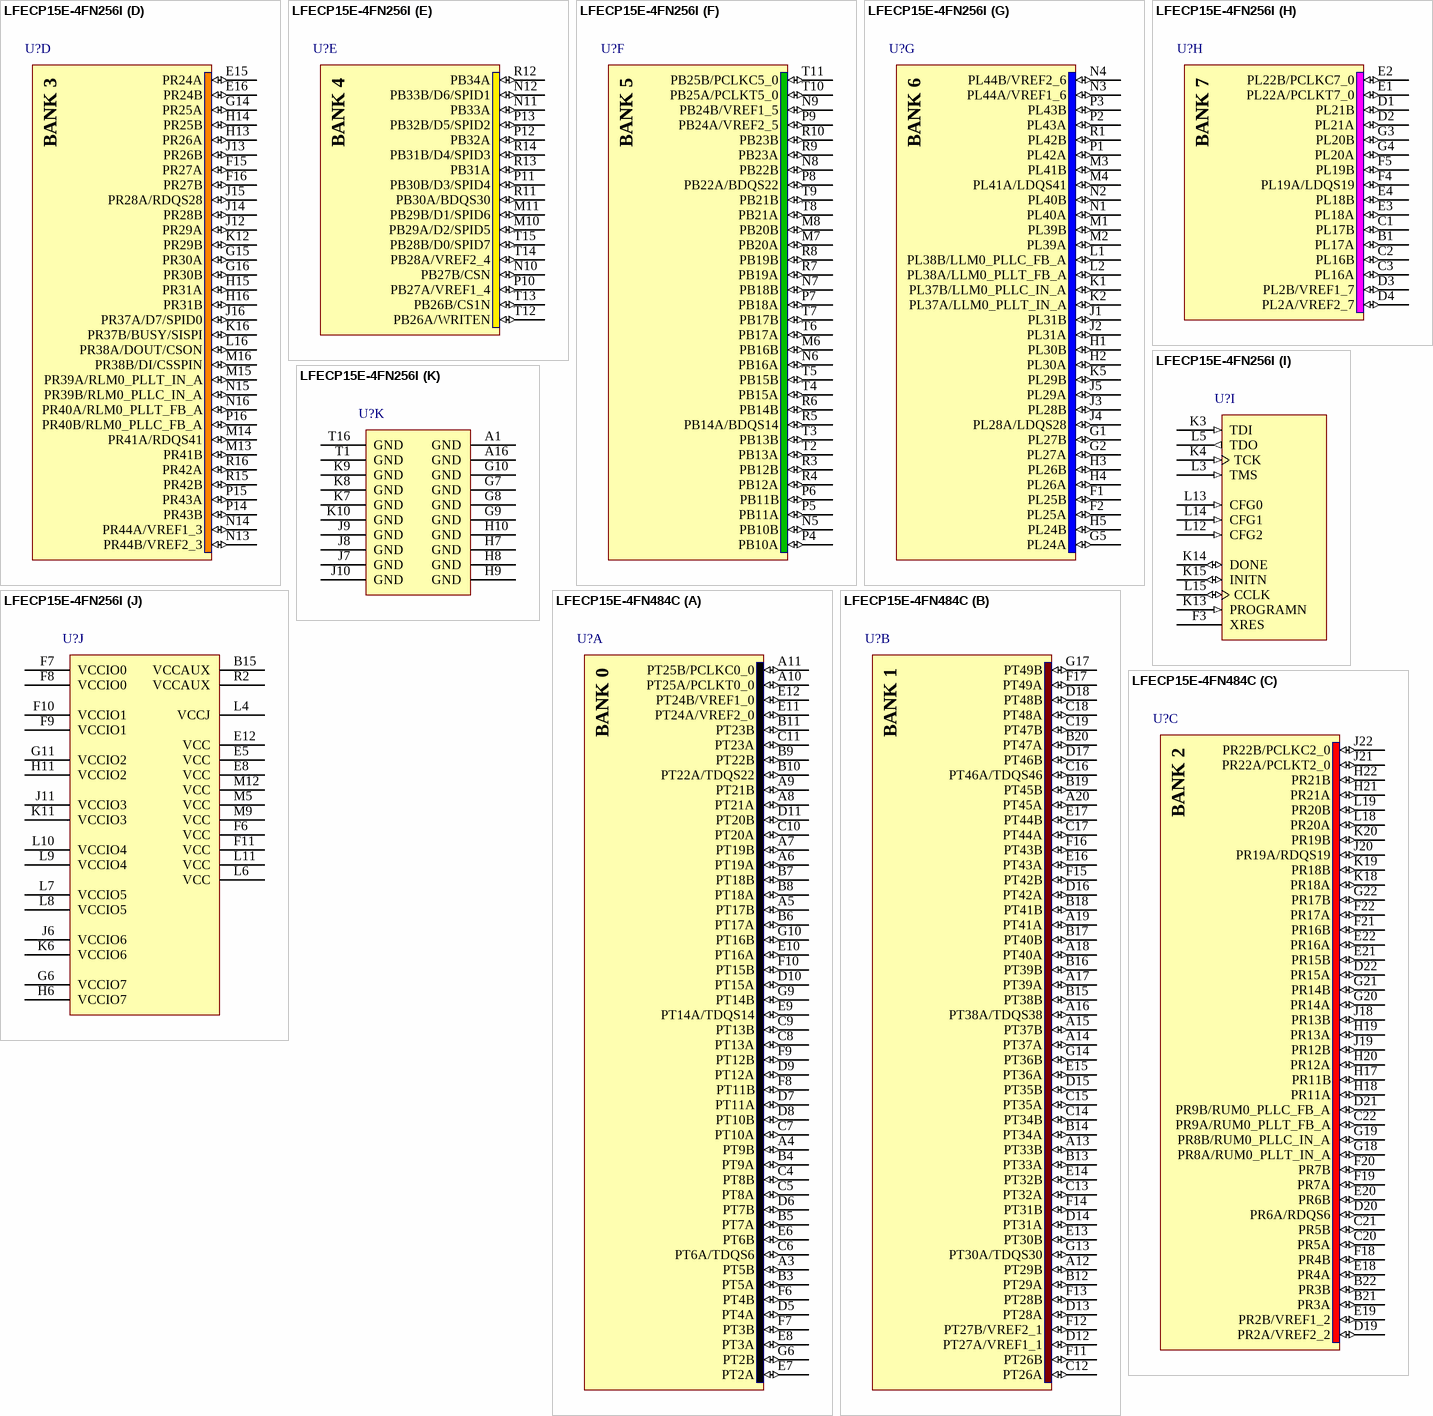
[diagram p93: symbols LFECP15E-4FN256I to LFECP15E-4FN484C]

## LFECP15E-4FN256I
designator U?
ECP 1.2V FPGA, 195 I/Os, 4 PLLs, 15.3K LUTs, 6 sysDSP Blocks, 24 18x18 Multipliers, 256-Pin fpBGA, Pb-Free, Speed Grade 4, Industrial Temperature Grade
footprint fpBGA256 (BGA, 256-Leads, Body 17x17mm, Pitch 1mm)
3D model ECP15E-fpBGA256 (256-Ball Fine Pitch Ball Grid Array (fpBGA256))
part A pins: A2 PT13A (io), A3 PT13B (io), A4 PT14A/TDQS14 (io), A5 PT14B (io), A6 PT18A (io), A7 PT18B (io), A8 PT21A (io), A9 PT21B (io), A10 PT25B/PCLKC0_0 (io), B2 PT12B (io), B3 PT12A (io), B4 PT10A (io), B5 PT15A (io), B6 PT15B (io), B7 PT20A (io), B8 PT20B (io), B9 PT24A/VREF2_0 (io), B10 PT25A/PCLKT0_0 (io), C4 PT10B (io), C5 PT11A (io), C6 PT16A (io), C7 PT19A (io), C8 PT22A/TDQS22 (io), C9 PT24B/VREF1_0 (io), D5 PT11B (io), D6 PT16B (io), D7 PT19B (io), D8 PT22B (io), D9 PT23A (io), E6 PT17A (io), E7 PT17B (io), E9 PT23B (io)
part B pins: A11 PT26B (io), A12 PT27B/VREF2_1 (io), A13 PT29A (io), A14 PT29B (io), A15 PT32B (io), B11 PT26A (io), B12 PT27A/VREF1_1 (io), B13 PT34B (io), B14 PT32A (io), C10 PT28A (io), C11 PT31A (io), C12 PT33B (io), C13 PT34A (io), D10 PT28B (io), D11 PT31B (io), D12 PT33A (io), E10 PT30B (io), E11 PT30A/TDQS30 (io)
part C pins: B16 PR17A (io), C14 PR16A (io), C15 PR16B (io), C16 PR17B (io), D13 PR2A/VREF2_2 (io), D14 PR2B/VREF1_2 (io), D15 PR19A/RDQS19 (io), D16 PR19B (io), E13 PR20A (io), E14 PR18A (io), F12 PR20B (io), F13 PR21A (io), F14 PR18B (io), G12 PR22A/PCLKT2_0 (io), G13 PR21B (io), H12 PR22B/PCLKC2_0 (io)
part D pins: E15 PR24A (io), E16 PR24B (io), F15 PR27A (io), F16 PR27B (io), G14 PR25A (io), G15 PR30A (io), G16 PR30B (io), H13 PR26A (io), H14 PR25B (io), H15 PR31A (io), H16 PR31B (io), J12 PR29A (io), J13 PR26B (io), J14 PR28B (io), J15 PR28A/RDQS28 (io), J16 PR37A/D7/SPID0 (io), K12 PR29B (io), K16 PR37B/BUSY/SISPI (io), L16 PR38A/DOUT/CSON (io), M13 PR41B (io), M14 PR41A/RDQS41 (io), M15 PR39A/RLM0_PLLT_IN_A (io), M16 PR38B/DI/CSSPIN (io), N13 PR44B/VREF2_3 (io), N14 PR44A/VREF1_3 (io), N15 PR39B/RLM0_PLLC_IN_A (io), N16 PR40A/RLM0_PLLT_FB_A (io), P14 PR43B (io), P15 PR43A (io), P16 PR40B/RLM0_PLLC_FB_A (io), R15 PR42B (io), R16 PR42A (io)
part E pins: M10 PB29A/D2/SPID5 (io), M11 PB29B/D1/SPID6 (io), N10 PB27B/CSN (io), N11 PB33A (io), N12 PB33B/D6/SPID1 (io), P10 PB27A/VREF1_4 (io), P11 PB30B/D3/SPID4 (io), P12 PB32A (io), P13 PB32B/D5/SPID2 (io), R11 PB30A/BDQS30 (io), R12 PB34A (io), R13 PB31A (io), R14 PB31B/D4/SPID3 (io), T12 PB26A/WRITEN (io), T13 PB26B/CS1N (io), T14 PB28A/VREF2_4 (io), T15 PB28B/D0/SPID7 (io)
part F pins: M6 PB16B (io), M7 PB20A (io), M8 PB20B (io), N5 PB10B (io), N6 PB16A (io), N7 PB18B (io), N8 PB22B (io), N9 PB24B/VREF1_5 (io), P4 PB10A (io), P5 PB11A (io), P6 PB11B (io), P7 PB18A (io), P8 PB22A/BDQS22 (io), P9 PB24A/VREF2_5 (io), R3 PB12B (io), R4 PB12A (io), R5 PB14A/BDQS14 (io), R6 PB14B (io), R7 PB19A (io), R8 PB19B (io), R9 PB23A (io), R10 PB23B (io), T2 PB13A (io), T3 PB13B (io), T4 PB15A (io), T5 PB15B (io), T6 PB17A (io), T7 PB17B (io), T8 PB21A (io), T9 PB21B (io), T10 PB25A/PCLKT5_0 (io), T11 PB25B/PCLKC5_0 (io)
part G pins: F1 PL25B (io), F2 PL25A (io), G1 PL27B (io), G2 PL27A (io), G5 PL24A (io), H1 PL30B (io), H2 PL30A (io), H3 PL26B (io), H4 PL26A (io), H5 PL24B (io), J1 PL31B (io), J2 PL31A (io), J3 PL28B (io), J4 PL28A/LDQS28 (io), J5 PL29A (io), K1 PL37B/LLM0_PLLC_IN_A (io), K2 PL37A/LLM0_PLLT_IN_A (io), K5 PL29B (io), L1 PL38B/LLM0_PLLC_FB_A (io), L2 PL38A/LLM0_PLLT_FB_A (io), M1 PL39B (io), M2 PL39A (io), M3 PL41B (io), M4 PL41A/LDQS41 (io), N1 PL40A (io), N2 PL40B (io), N3 PL44A/VREF1_6 (io), N4 PL44B/VREF2_6 (io), P1 PL42A (io), P2 PL43A (io), P3 PL43B (io), R1 PL42B (io)
part H pins: B1 PL17A (io), C1 PL17B (io), C2 PL16B (io), C3 PL16A (io), D1 PL21B (io), D2 PL21A (io), D3 PL2B/VREF1_7 (io), D4 PL2A/VREF2_7 (io), E1 PL22A/PCLKT7_0 (io), E2 PL22B/PCLKC7_0 (io), E3 PL18A (io), E4 PL18B (io), F4 PL19A/LDQS19 (io), F5 PL19B (io), G3 PL20B (io), G4 PL20A (io)
part I pins: F3 XRES, K3 TDI (in), K4 TCK (in), K13 PROGRAMN (in), K14 DONE (io), K15 INITN (io), L3 TMS (in), L5 TDO (out), L12 CFG2 (in), L13 CFG0 (in), L14 CFG1 (in), L15 CCLK (io)
part J pins: B15 VCCAUX (power), E5 VCC (power), E8 VCC (power), E12 VCC (power), F6 VCC (power), F7 VCCIO0 (power), F8 VCCIO0 (power), F9 VCCIO1 (power), F10 VCCIO1 (power), F11 VCC (power), G6 VCCIO7 (power), G11 VCCIO2 (power), H6 VCCIO7 (power), H11 VCCIO2 (power), J6 VCCIO6 (power), J11 VCCIO3 (power), K6 VCCIO6 (power), K11 VCCIO3 (power), L4 VCCJ (power), L6 VCC (power), L7 VCCIO5 (power), L8 VCCIO5 (power), L9 VCCIO4 (power), L10 VCCIO4 (power), L11 VCC (power), M5 VCC (power), M9 VCC (power), M12 VCC (power), R2 VCCAUX (power)
part K pins: A1 GND (power), A16 GND (power), G7 GND (power), G8 GND (power), G9 GND (power), G10 GND (power), H7 GND (power), H8 GND (power), H9 GND (power), H10 GND (power), J7 GND (power), J8 GND (power), J9 GND (power), J10 GND (power), K7 GND (power), K8 GND (power), K9 GND (power), K10 GND (power), T1 GND (power), T16 GND (power)

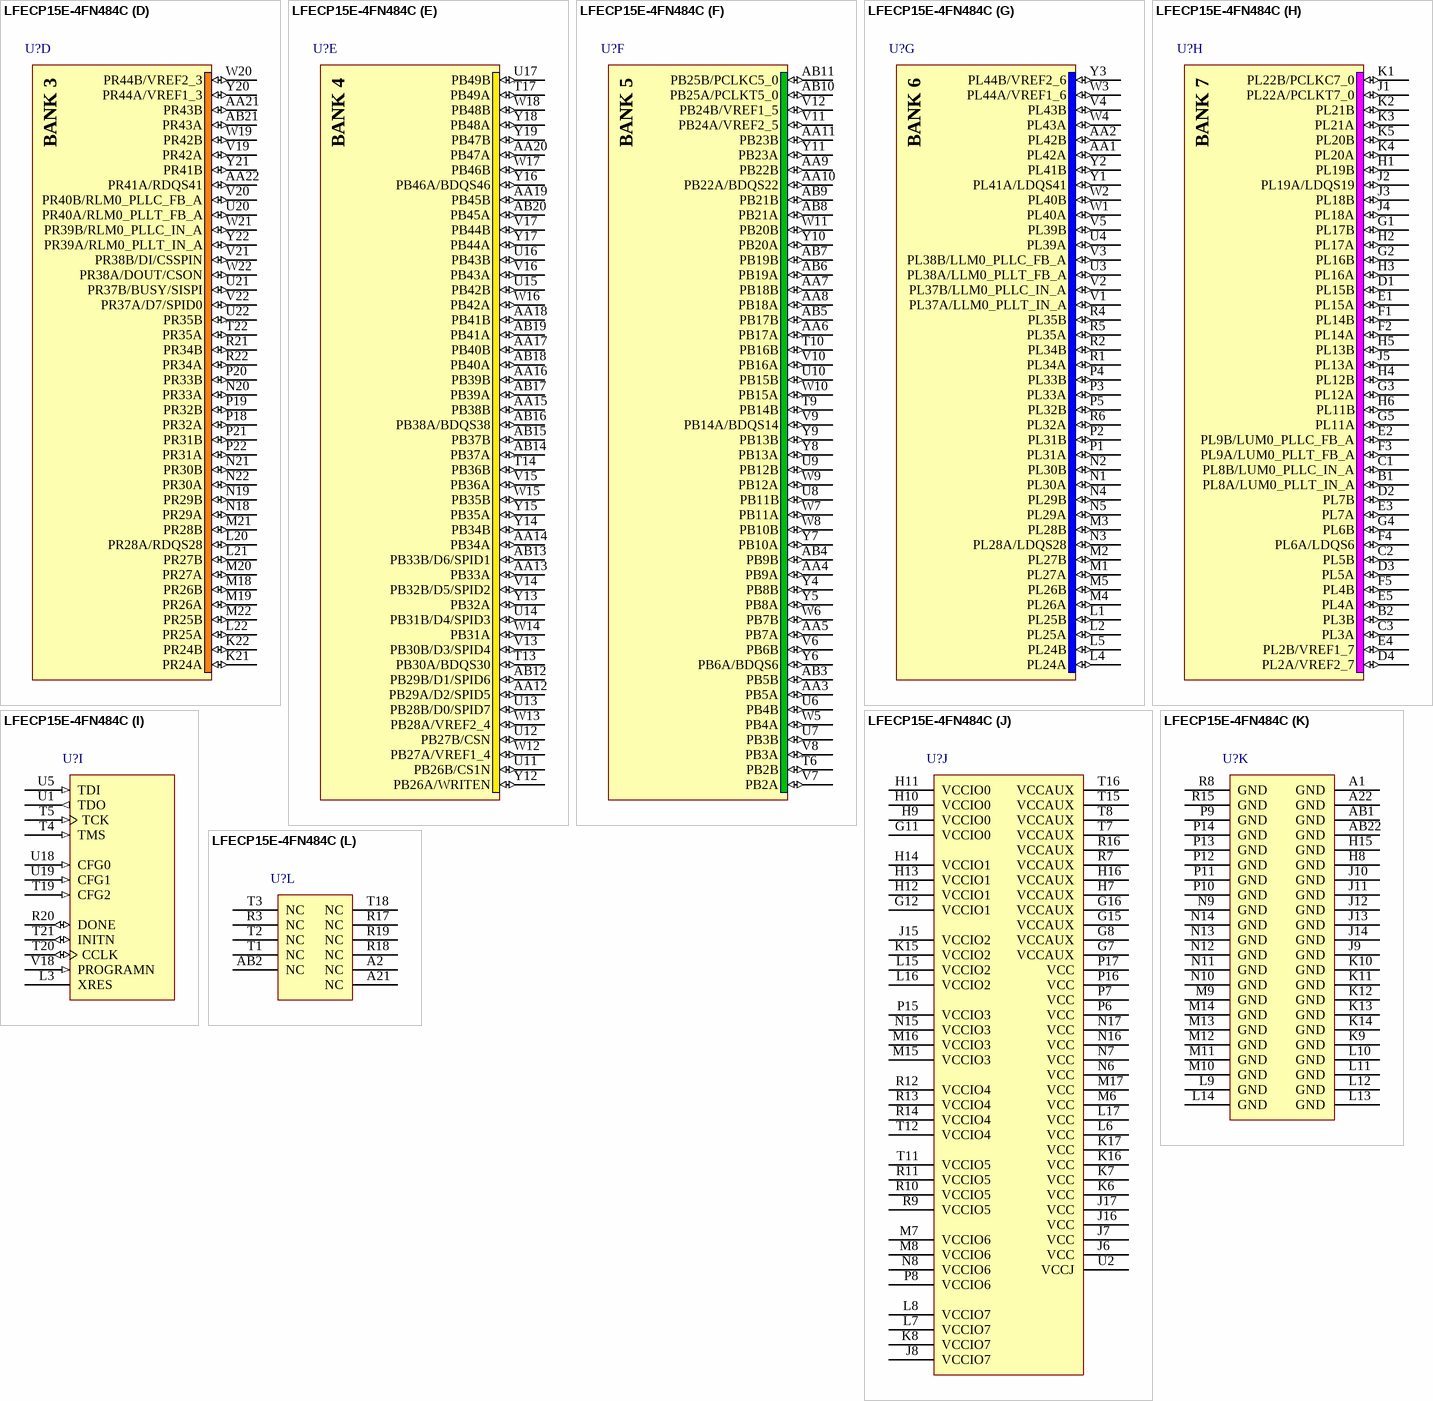
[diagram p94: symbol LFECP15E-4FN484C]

## LFECP15E-4FN484C
designator U?
ECP 1.2V FPGA, 352 I/Os, 4 PLLs, 15.3K LUTs, 6 sysDSP Blocks, 24 18x18 Multipliers, 484-Pin fpBGA, Pb-Free, Speed Grade 4, Commercial Temperature Grade
footprint fpBGA484 (BGA, 484-Leads, Body 23x23mm, Pitch 1mm)
3D model ECP15E-fpBGA484 (484-Ball Fine Pitch Ball Grid Array (fpBGA484))
part A pins: A3 PT5B (io), A4 PT9B (io), A5 PT17B (io), A6 PT19A (io), A7 PT19B (io), A8 PT21A (io), A9 PT21B (io), A10 PT25A/PCLKT0_0 (io), A11 PT25B/PCLKC0_0 (io), B3 PT5A (io), B4 PT9A (io), B5 PT7A (io), B6 PT17A (io), B7 PT18B (io), B8 PT18A (io), B9 PT22B (io), B10 PT22A/TDQS22 (io), B11 PT23B (io), C4 PT8B (io), C5 PT8A (io), C6 PT6A/TDQS6 (io), C7 PT10A (io), C8 PT13A (io), C9 PT13B (io), C10 PT20A (io), C11 PT23A (io), D5 PT4A (io), D6 PT7B (io), D7 PT11A (io), D8 PT10B (io), D9 PT12A (io), D10 PT15A (io), D11 PT20B (io), E6 PT6B (io), E7 PT2A (io), E8 PT3A (io), E9 PT14A/TDQS14 (io), E10 PT16A (io), E11 PT24A/VREF2_0 (io), E12 PT24B/VREF1_0 (io), F6 PT4B (io), F7 PT3B (io), F8 PT11B (io), F9 PT12B (io), F10 PT15B (io), G6 PT2B (io), G9 PT14B (io), G10 PT16B (io)
part B pins: A12 PT29B (io), A13 PT33B (io), A14 PT37A (io), A15 PT37B (io), A16 PT38A/TDQS38 (io), A17 PT39A (io), A18 PT40A (io), A19 PT41A (io), A20 PT45A (io), B12 PT29A (io), B13 PT33A (io), B14 PT34A (io), B15 PT38B (io), B16 PT39B (io), B17 PT40B (io), B18 PT41B (io), B19 PT45B (io), B20 PT47A (io), C12 PT26A (io), C13 PT32A (io), C14 PT34B (io), C15 PT35A (io), C16 PT46A/TDQS46 (io), C17 PT44A (io), C18 PT48A (io), C19 PT47B (io), D12 PT27A/VREF1_1 (io), D13 PT28A (io), D14 PT31A (io), D15 PT35B (io), D16 PT42A (io), D17 PT46B (io), D18 PT48B (io), E13 PT30B (io), E14 PT32B (io), E15 PT36A (io), E16 PT43A (io), E17 PT44B (io), F11 PT26B (io), F12 PT27B/VREF2_1 (io), F13 PT28B (io), F14 PT31B (io), F15 PT42B (io), F16 PT43B (io), F17 PT49A (io), G13 PT30A/TDQS30 (io), G14 PT36B (io), G17 PT49B (io)
part C pins: B21 PR3A (io), B22 PR3B (io), C20 PR5A (io), C21 PR5B (io), C22 PR9A/RUM0_PLLT_FB_A (io), D19 PR2A/VREF2_2 (io), D20 PR6A/RDQS6 (io), D21 PR9B/RUM0_PLLC_FB_A (io), D22 PR15A (io), E18 PR4A (io), E19 PR2B/VREF1_2 (io), E20 PR6B (io), E21 PR15B (io), E22 PR16A (io), F18 PR4B (io), F19 PR7A (io), F20 PR7B (io), F21 PR16B (io), F22 PR17A (io), G18 PR8A/RUM0_PLLT_IN_A (io), G19 PR8B/RUM0_PLLC_IN_A (io), G20 PR14A (io), G21 PR14B (io), G22 PR17B (io), H17 PR11B (io), H18 PR11A (io), H19 PR13A (io), H20 PR12A (io), H21 PR21A (io), H22 PR21B (io), J18 PR13B (io), J19 PR12B (io), J20 PR19A/RDQS19 (io), J21 PR22A/PCLKT2_0 (io), J22 PR22B/PCLKC2_0 (io), K18 PR18A (io), K19 PR18B (io), K20 PR19B (io), L18 PR20A (io), L19 PR20B (io)
part D pins: AA21 PR43B (io), AA22 PR41A/RDQS41 (io), AB21 PR43A (io), K21 PR24A (io), K22 PR24B (io), L20 PR28A/RDQS28 (io), L21 PR27B (io), L22 PR25A (io), M18 PR26B (io), M19 PR26A (io), M20 PR27A (io), M21 PR28B (io), M22 PR25B (io), N18 PR29A (io), N19 PR29B (io), N20 PR33A (io), N21 PR30B (io), N22 PR30A (io), P18 PR32A (io), P19 PR32B (io), P20 PR33B (io), P21 PR31B (io), P22 PR31A (io), R21 PR34B (io), R22 PR34A (io), T22 PR35A (io), U20 PR40A/RLM0_PLLT_FB_A (io), U21 PR37B/BUSY/SISPI (io), U22 PR35B (io), V19 PR42A (io), V20 PR40B/RLM0_PLLC_FB_A (io), V21 PR38B/DI/CSSPIN (io), V22 PR37A/D7/SPID0 (io), W19 PR42B (io), W20 PR44B/VREF2_3 (io), W21 PR39B/RLM0_PLLC_IN_A (io), W22 PR38A/DOUT/CSON (io), Y20 PR44A/VREF1_3 (io), Y21 PR41B (io), Y22 PR39A/RLM0_PLLT_IN_A (io)
part E pins: AA12 PB29A/D2/SPID5 (io), AA13 PB33A (io), AA14 PB34A (io), AA15 PB38B (io), AA16 PB39B (io), AA17 PB40B (io), AA18 PB41B (io), AA19 PB45B (io), AA20 PB47A (io), AB12 PB29B/D1/SPID6 (io), AB13 PB33B/D6/SPID1 (io), AB14 PB37A (io), AB15 PB37B (io), AB16 PB38A/BDQS38 (io), AB17 PB39A (io), AB18 PB40A (io), AB19 PB41A (io), AB20 PB45A (io), T13 PB30A/BDQS30 (io), T14 PB36B (io), T17 PB49A (io), U11 PB26B/CS1N (io), U12 PB27B/CSN (io), U13 PB28B/D0/SPID7 (io), U14 PB31B/D4/SPID3 (io), U15 PB42B (io), U16 PB43B (io), U17 PB49B (io), V13 PB30B/D3/SPID4 (io), V14 PB32B/D5/SPID2 (io), V15 PB36A (io), V16 PB43A (io), V17 PB44B (io), W12 PB27A/VREF1_4 (io), W13 PB28A/VREF2_4 (io), W14 PB31A (io), W15 PB35B (io), W16 PB42A (io), W17 PB46B (io), W18 PB48B (io), Y12 PB26A/WRITEN (io), Y13 PB32A (io), Y14 PB34B (io), Y15 PB35A (io), Y16 PB46A/BDQS46 (io), Y17 PB44A (io), Y18 PB48A (io), Y19 PB47B (io)
part F pins: AA3 PB5A (io), AA4 PB9A (io), AA5 PB7A (io), AA6 PB17A (io), AA7 PB18B (io), AA8 PB18A (io), AA9 PB22B (io), AA10 PB22A/BDQS22 (io), AA11 PB23B (io), AB3 PB5B (io), AB4 PB9B (io), AB5 PB17B (io), AB6 PB19A (io), AB7 PB19B (io), AB8 PB21A (io), AB9 PB21B (io), AB10 PB25A/PCLKT5_0 (io), AB11 PB25B/PCLKC5_0 (io), T6 PB2B (io), T9 PB14B (io), T10 PB16B (io), U6 PB4B (io), U7 PB3B (io), U8 PB11B (io), U9 PB12B (io), U10 PB15B (io), V6 PB6B (io), V7 PB2A (io), V8 PB3A (io), V9 PB14A/BDQS14 (io), V10 PB16A (io), V11 PB24A/VREF2_5 (io), V12 PB24B/VREF1_5 (io), W5 PB4A (io), W6 PB7B (io), W7 PB11A (io), W8 PB10B (io), W9 PB12A (io), W10 PB15A (io), W11 PB20B (io), Y4 PB8B (io), Y5 PB8A (io), Y6 PB6A/BDQS6 (io), Y7 PB10A (io), Y8 PB13A (io), Y9 PB13B (io), Y10 PB20A (io), Y11 PB23A (io)
part G pins: AA1 PL42A (io), AA2 PL42B (io), L1 PL25B (io), L2 PL25A (io), L4 PL24A (io), L5 PL24B (io), M1 PL27A (io), M2 PL27B (io), M3 PL28B (io), M4 PL26A (io), M5 PL26B (io), N1 PL30A (io), N2 PL30B (io), N3 PL28A/LDQS28 (io), N4 PL29B (io), N5 PL29A (io), P1 PL31A (io), P2 PL31B (io), P3 PL33A (io), P4 PL33B (io), P5 PL32B (io), R1 PL34A (io), R2 PL34B (io), R4 PL35B (io), R5 PL35A (io), R6 PL32A (io), U3 PL38A/LLM0_PLLT_FB_A (io), U4 PL39A (io), V1 PL37A/LLM0_PLLT_IN_A (io), V2 PL37B/LLM0_PLLC_IN_A (io), V3 PL38B/LLM0_PLLC_FB_A (io), V4 PL43B (io), V5 PL39B (io), W1 PL40A (io), W2 PL40B (io), W3 PL44A/VREF1_6 (io), W4 PL43A (io), Y1 PL41A/LDQS41 (io), Y2 PL41B (io), Y3 PL44B/VREF2_6 (io)
part H pins: B1 PL8A/LUM0_PLLT_IN_A (io), B2 PL3B (io), C1 PL8B/LUM0_PLLC_IN_A (io), C2 PL5B (io), C3 PL3A (io), D1 PL15B (io), D2 PL7B (io), D3 PL5A (io), D4 PL2A/VREF2_7 (io), E1 PL15A (io), E2 PL9B/LUM0_PLLC_FB_A (io), E3 PL7A (io), E4 PL2B/VREF1_7 (io), E5 PL4A (io), F1 PL14B (io), F2 PL14A (io), F3 PL9A/LUM0_PLLT_FB_A (io), F4 PL6A/LDQS6 (io), F5 PL4B (io), G1 PL17B (io), G2 PL16B (io), G3 PL12A (io), G4 PL6B (io), G5 PL11A (io), H1 PL19B (io), H2 PL17A (io), H3 PL16A (io), H4 PL12B (io), H5 PL13B (io), H6 PL11B (io), J1 PL22A/PCLKT7_0 (io), J2 PL19A/LDQS19 (io), J3 PL18B (io), J4 PL18A (io), J5 PL13A (io), K1 PL22B/PCLKC7_0 (io), K2 PL21B (io), K3 PL21A (io), K4 PL20A (io), K5 PL20B (io)
part I pins: L3 XRES, R20 DONE (io), T4 TMS (in), T5 TCK (in), T19 CFG2 (in), T20 CCLK (io), T21 INITN (io), U1 TDO (out), U5 TDI (in), U18 CFG0 (in), U19 CFG1 (in), V18 PROGRAMN (in)
part J pins: G7 VCCAUX (power), G8 VCCAUX (power), G11 VCCIO0 (power), G12 VCCIO1 (power), G15 VCCAUX (power), G16 VCCAUX (power), H7 VCCAUX (power), H9 VCCIO0 (power), H10 VCCIO0 (power), H11 VCCIO0 (power), H12 VCCIO1 (power), H13 VCCIO1 (power), H14 VCCIO1 (power), H16 VCCAUX (power), J6 VCC (power), J7 VCC (power), J8 VCCIO7 (power), J15 VCCIO2 (power), J16 VCC (power), J17 VCC (power), K6 VCC (power), K7 VCC (power), K8 VCCIO7 (power), K15 VCCIO2 (power), K16 VCC (power), K17 VCC (power), L6 VCC (power), L7 VCCIO7 (power), L8 VCCIO7 (power), L15 VCCIO2 (power), L16 VCCIO2 (power), L17 VCC (power), M6 VCC (power), M7 VCCIO6 (power), M8 VCCIO6 (power), M15 VCCIO3 (power), M16 VCCIO3 (power), M17 VCC (power), N6 VCC (power), N7 VCC (power), N8 VCCIO6 (power), N15 VCCIO3 (power), N16 VCC (power), N17 VCC (power), P6 VCC (power), P7 VCC (power), P8 VCCIO6 (power), P15 VCCIO3 (power), P16 VCC (power), P17 VCC (power), R7 VCCAUX (power), R9 VCCIO5 (power), R10 VCCIO5 (power), R11 VCCIO5 (power), R12 VCCIO4 (power), R13 VCCIO4 (power), R14 VCCIO4 (power), R16 VCCAUX (power), T7 VCCAUX (power), T8 VCCAUX (power), T11 VCCIO5 (power), T12 VCCIO4 (power), T15 VCCAUX (power), T16 VCCAUX (power), U2 VCCJ (power)
part K pins: A1 GND (power), A22 GND (power), AB1 GND (power), AB22 GND (power), H8 GND (power), H15 GND (power), J9 GND (power), J10 GND (power), J11 GND (power), J12 GND (power), J13 GND (power), J14 GND (power), K9 GND (power), K10 GND (power), K11 GND (power), K12 GND (power), K13 GND (power), K14 GND (power), L9 GND (power), L10 GND (power), L11 GND (power), L12 GND (power), L13 GND (power), L14 GND (power), M9 GND (power), M10 GND (power), M11 GND (power), M12 GND (power), M13 GND (power), M14 GND (power), N9 GND (power), N10 GND (power), N11 GND (power), N12 GND (power), N13 GND (power), N14 GND (power), P9 GND (power), P10 GND (power), P11 GND (power), P12 GND (power), P13 GND (power), P14 GND (power), R8 GND (power), R15 GND (power)
part L pins: A2 NC, A21 NC, AB2 NC, R3 NC, R17 NC, R18 NC, R19 NC, T1 NC, T2 NC, T3 NC, T18 NC

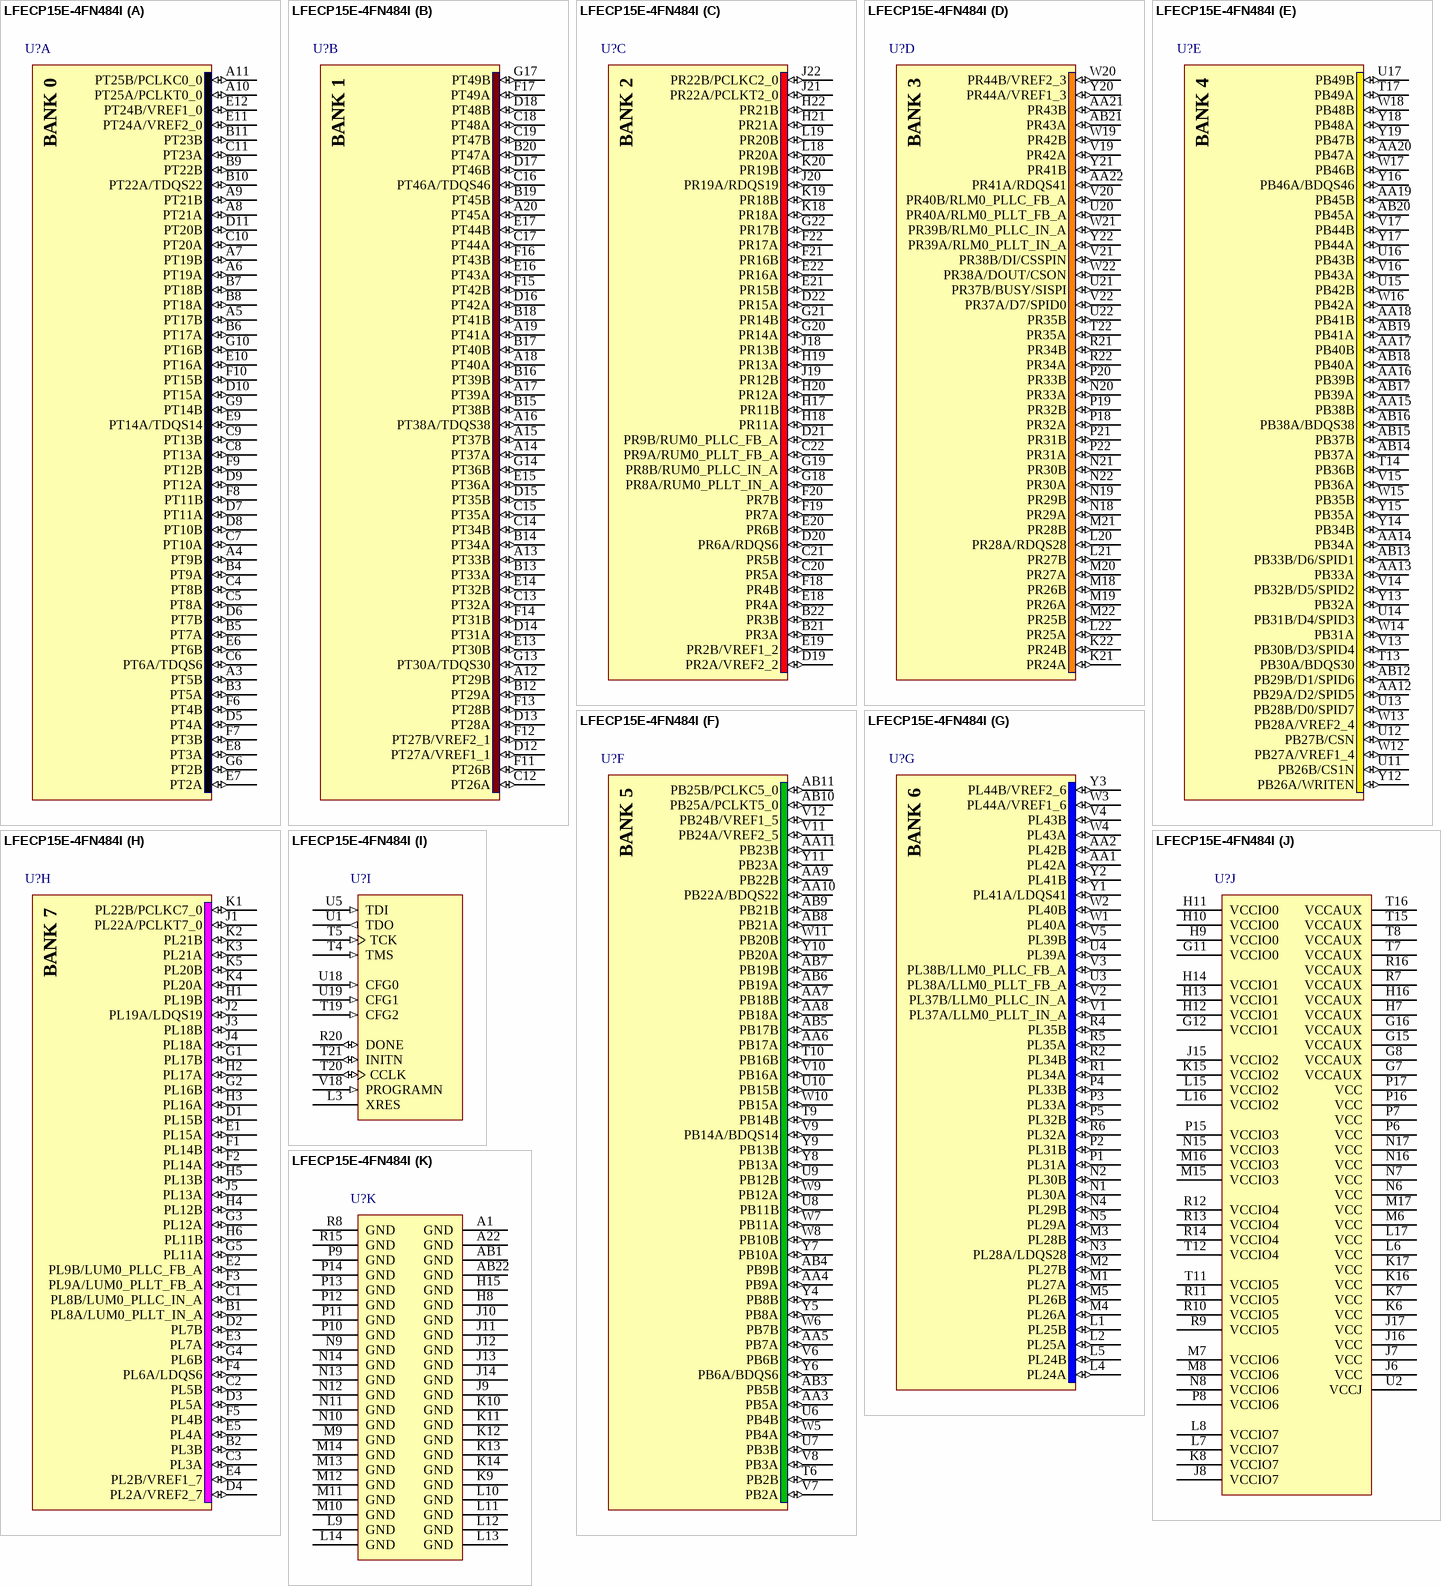
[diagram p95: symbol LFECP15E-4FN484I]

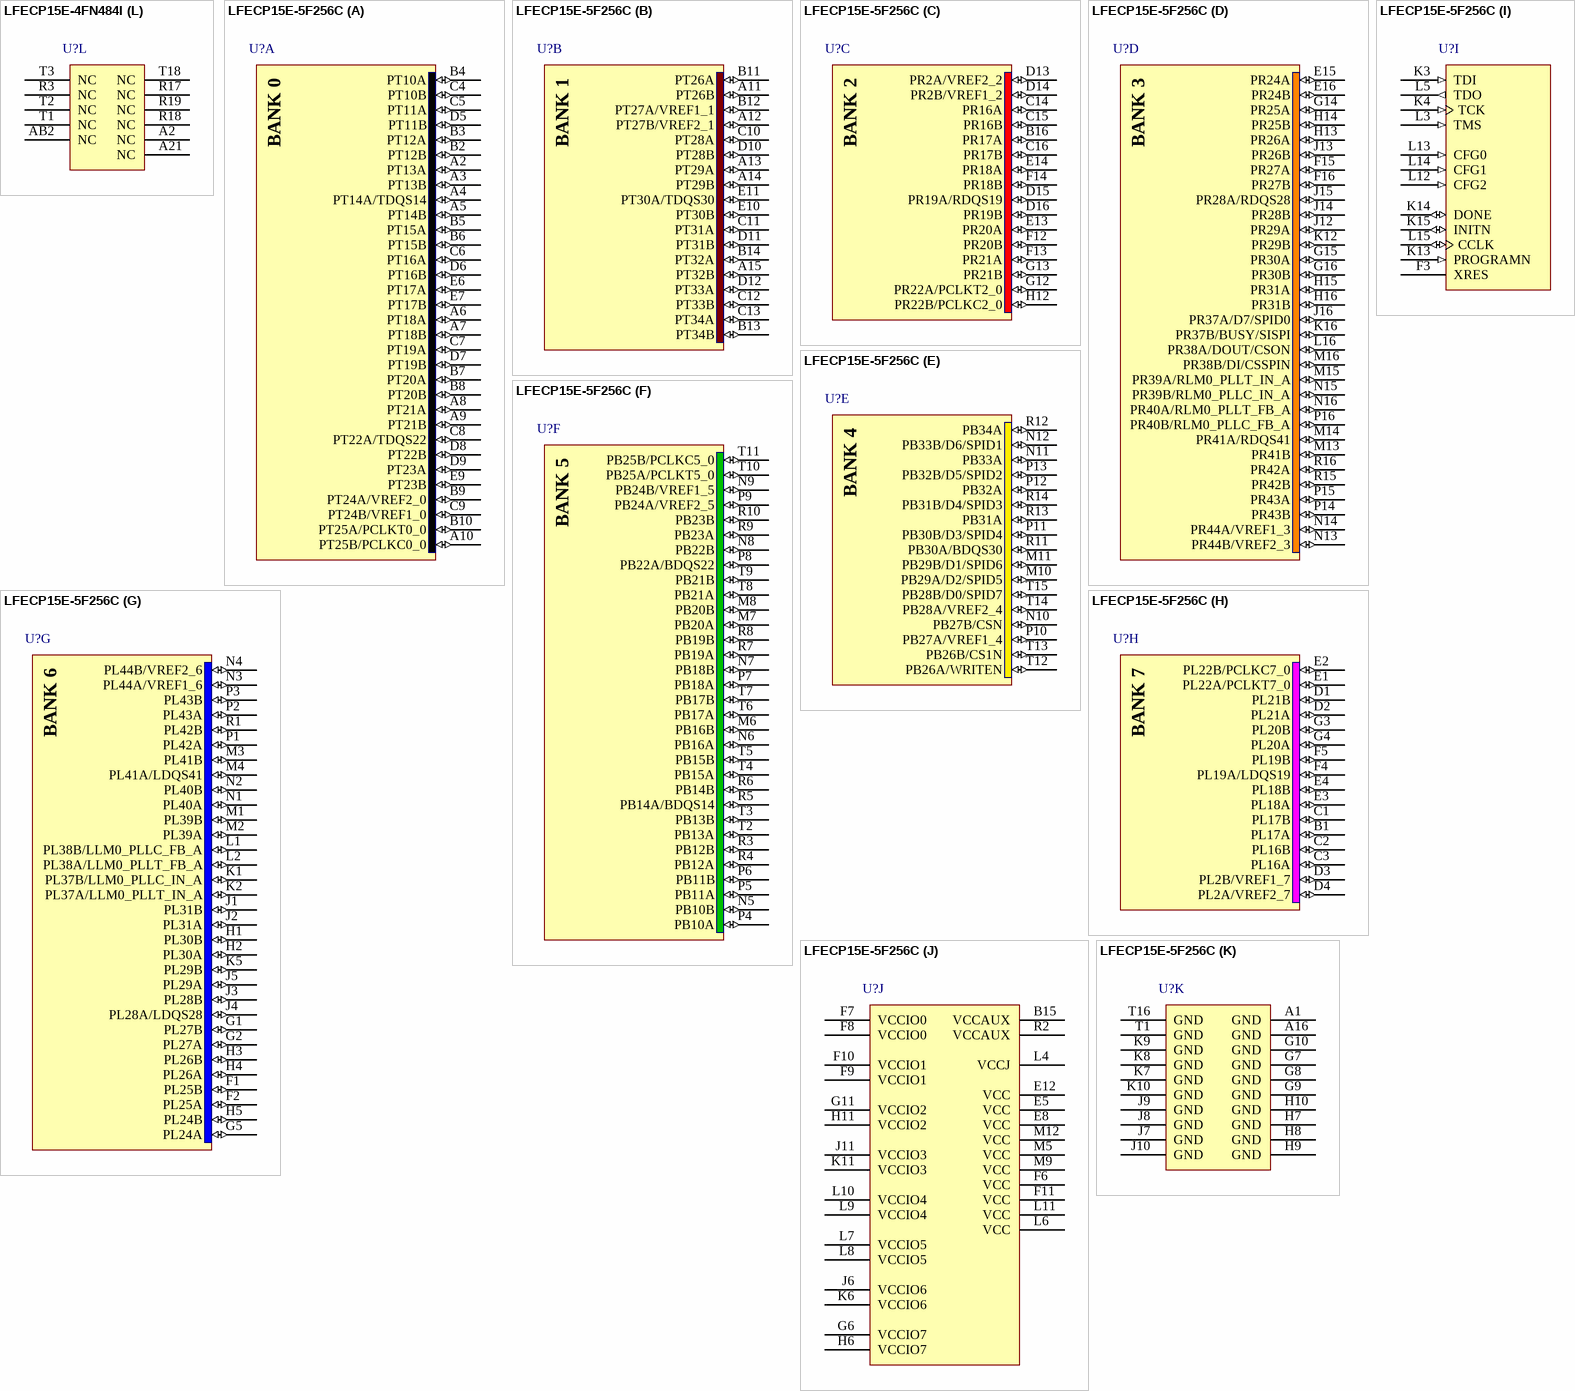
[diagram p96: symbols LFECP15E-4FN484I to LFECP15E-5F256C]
